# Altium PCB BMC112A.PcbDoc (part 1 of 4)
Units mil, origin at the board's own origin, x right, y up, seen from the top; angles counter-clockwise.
Board outline 5600 x 6100 mil, 8 copper layers (Top Layer, Signal Layer 1, Signal Layer 2, Signal Layer 3, Signal Layer 4, Signal Layer 5, Signal Layer 6, Bottom Layer), stack 62.048 mil thick; 366 components, 158 nets, 872 pads, 1045 vias.
Unrouted connection lines stored in the file: 4.
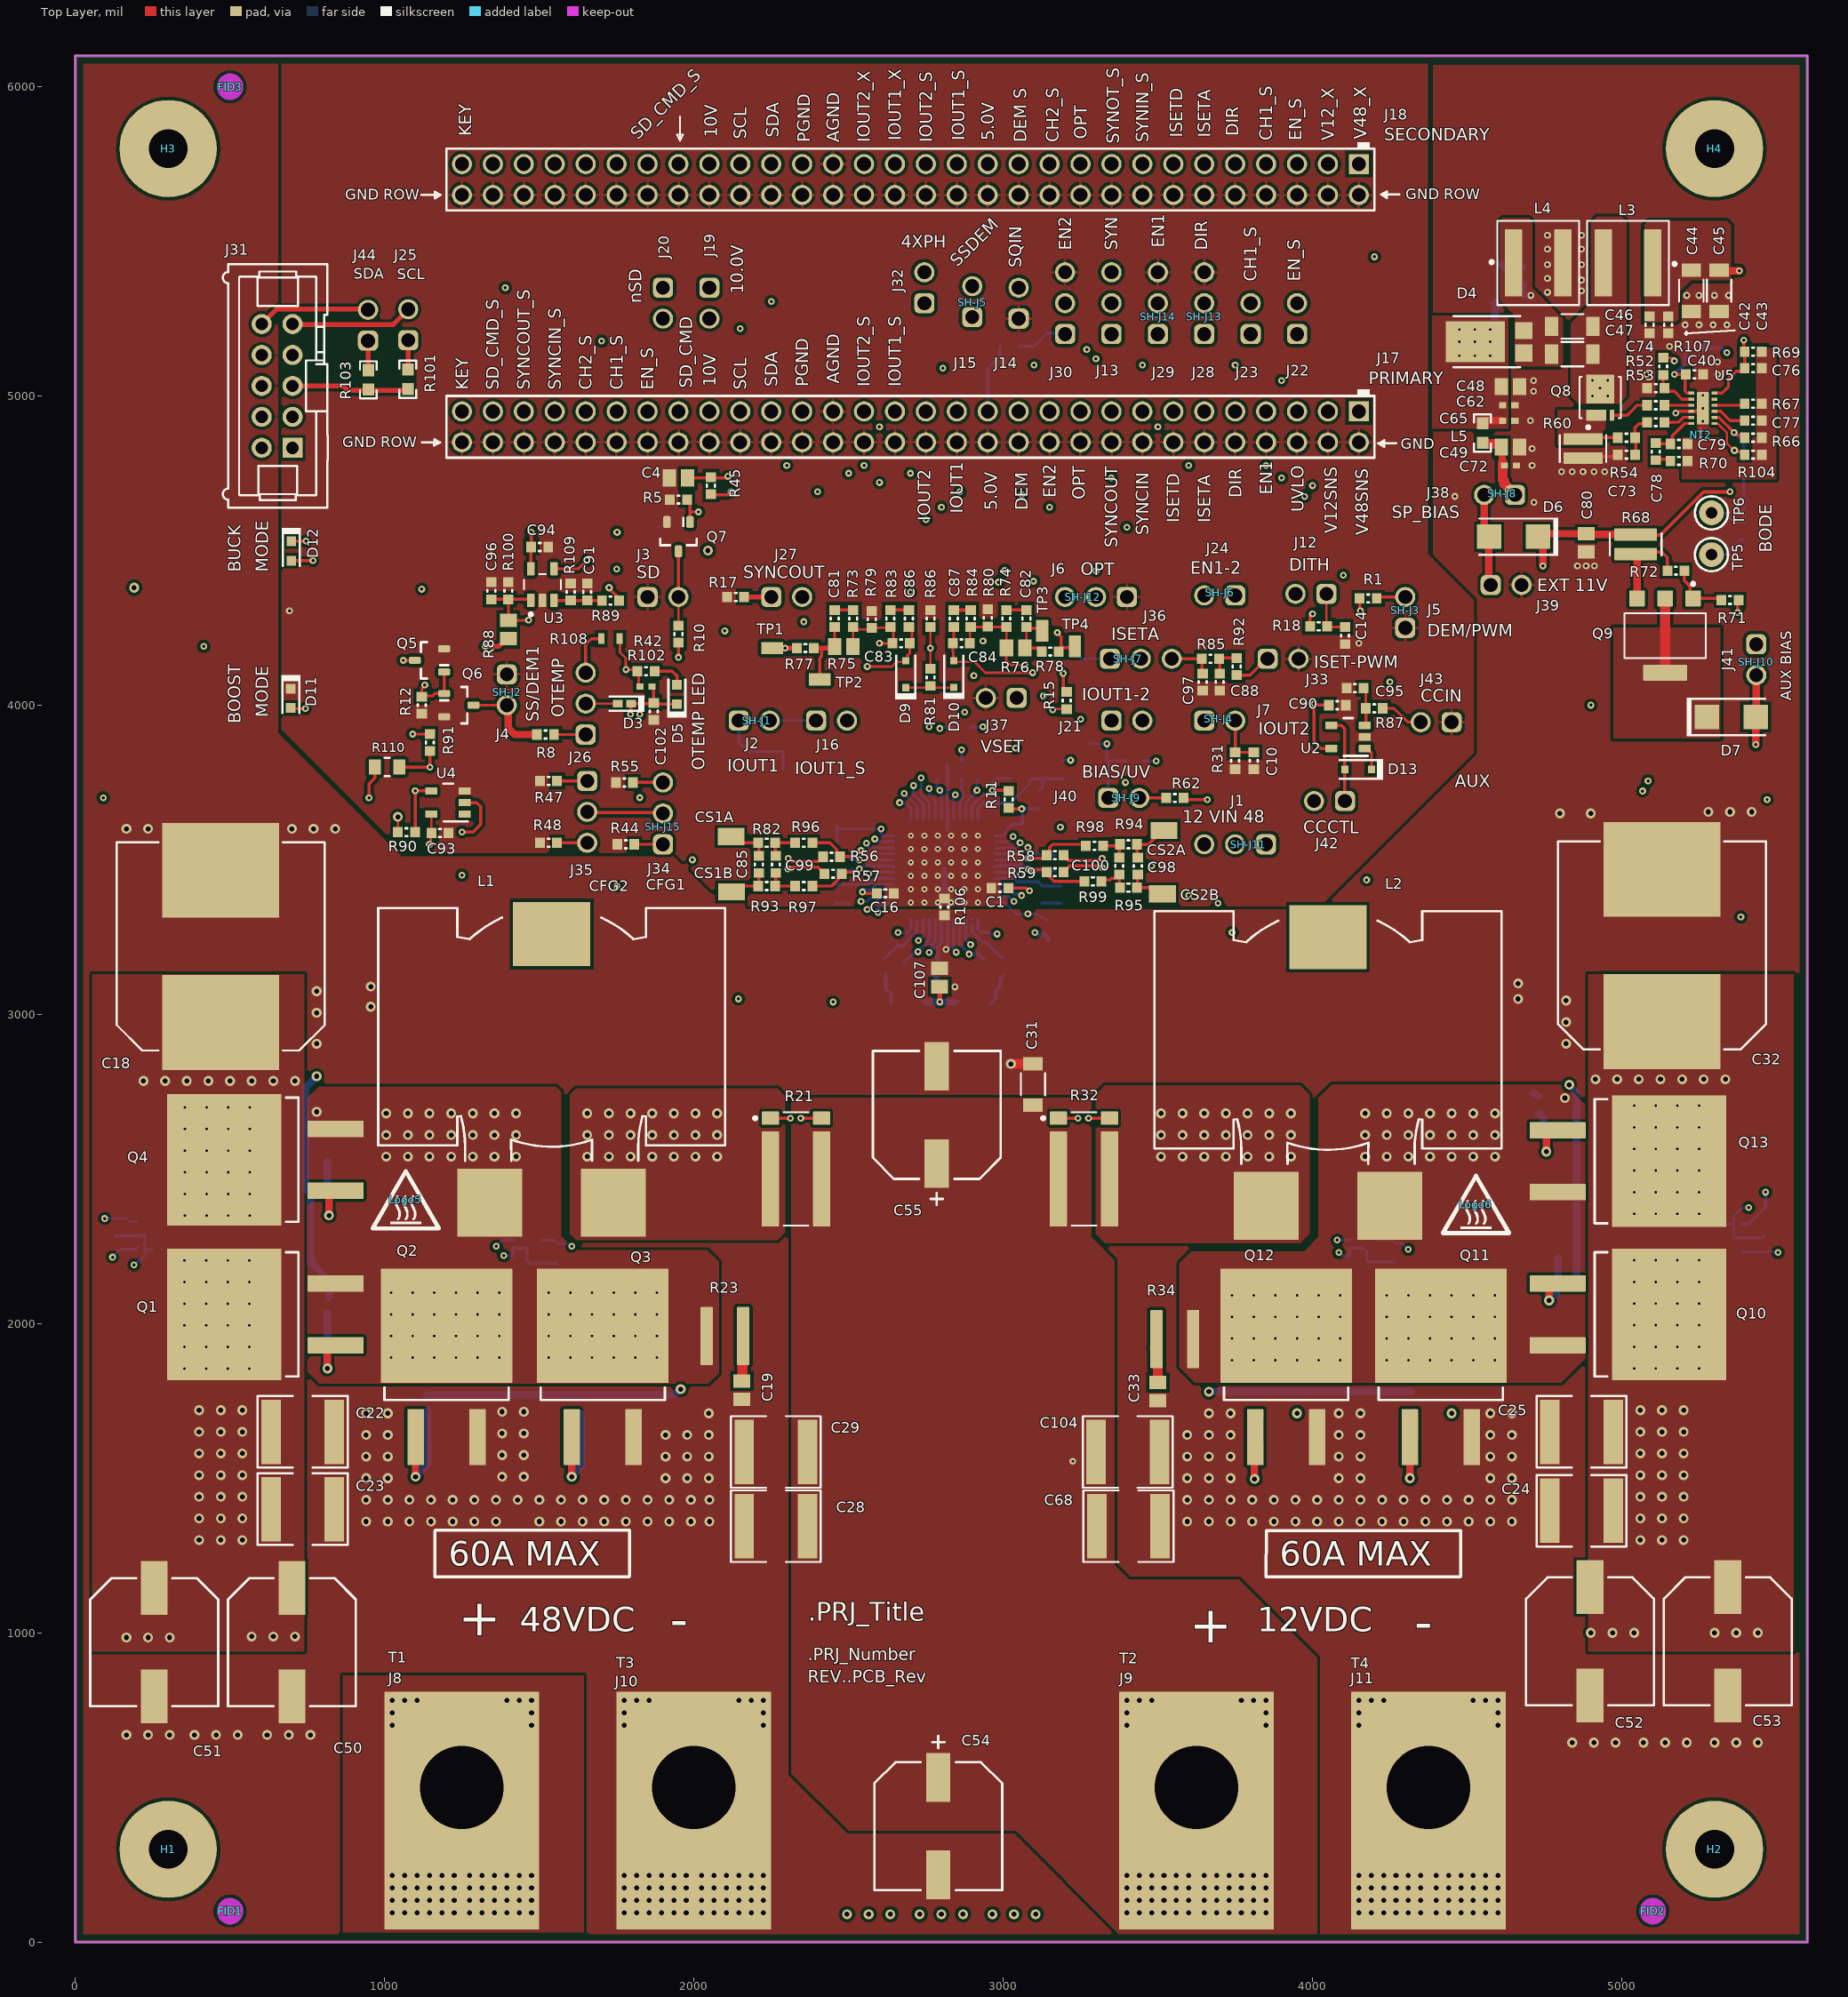
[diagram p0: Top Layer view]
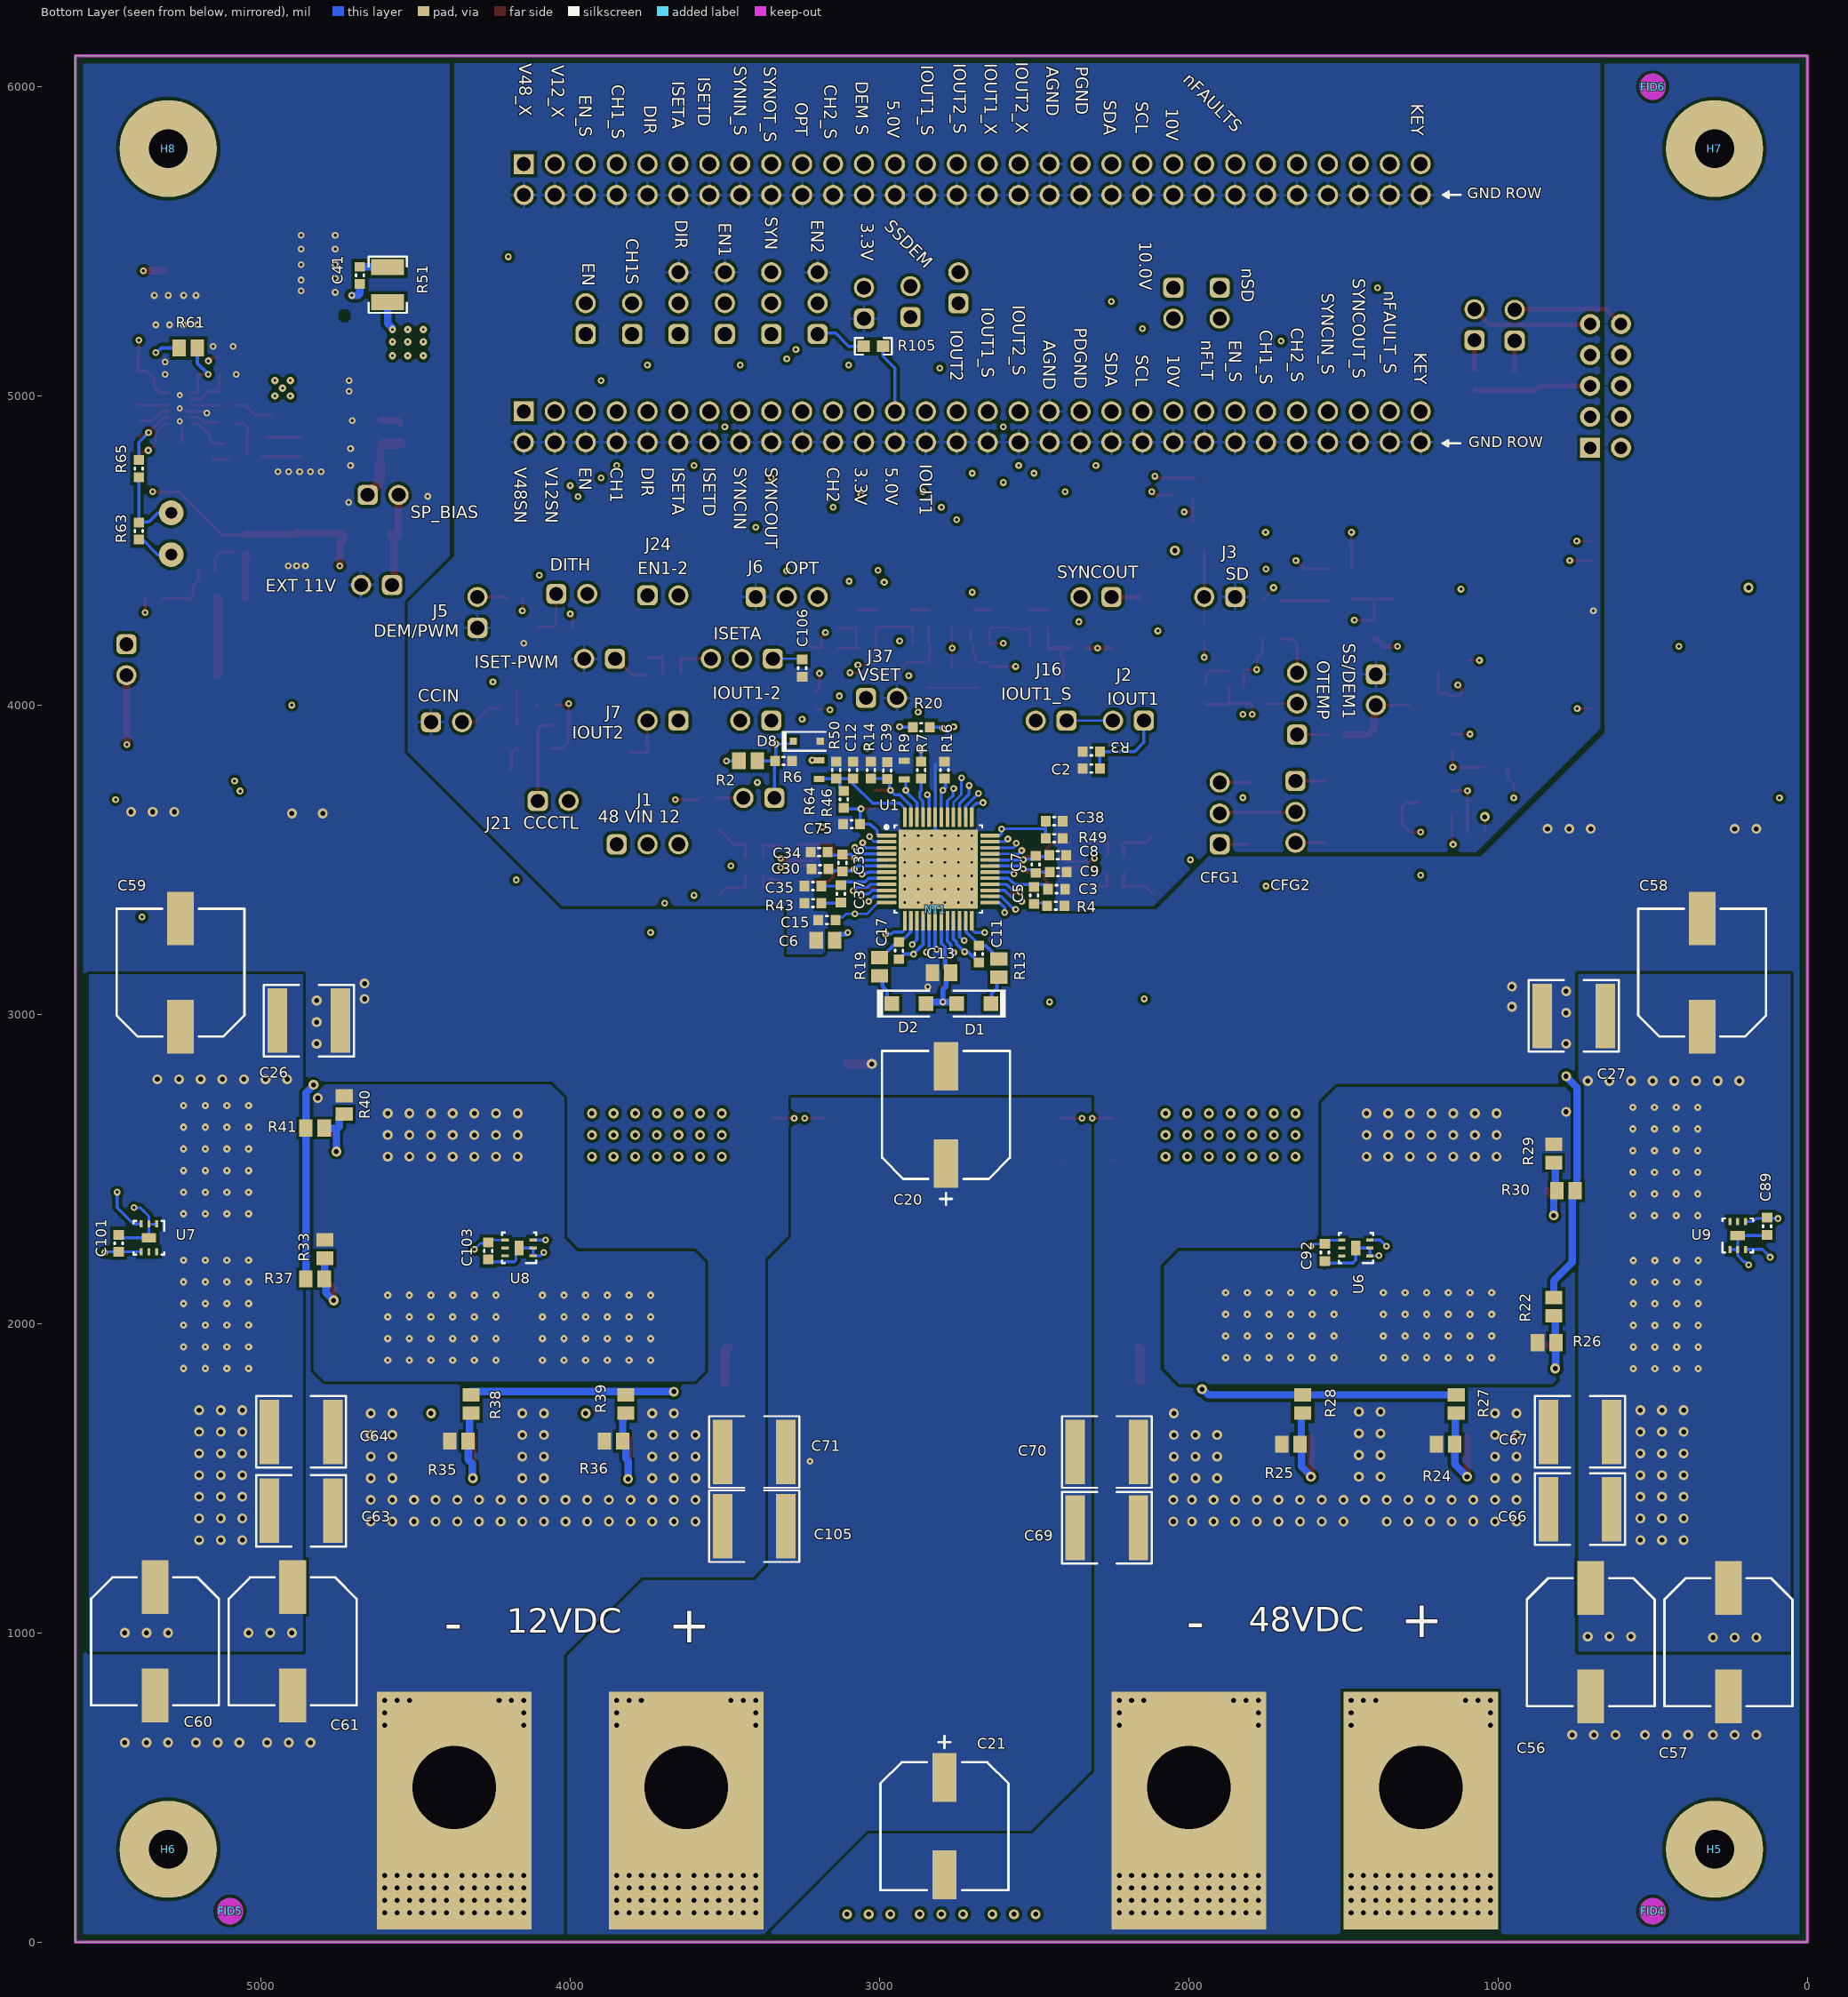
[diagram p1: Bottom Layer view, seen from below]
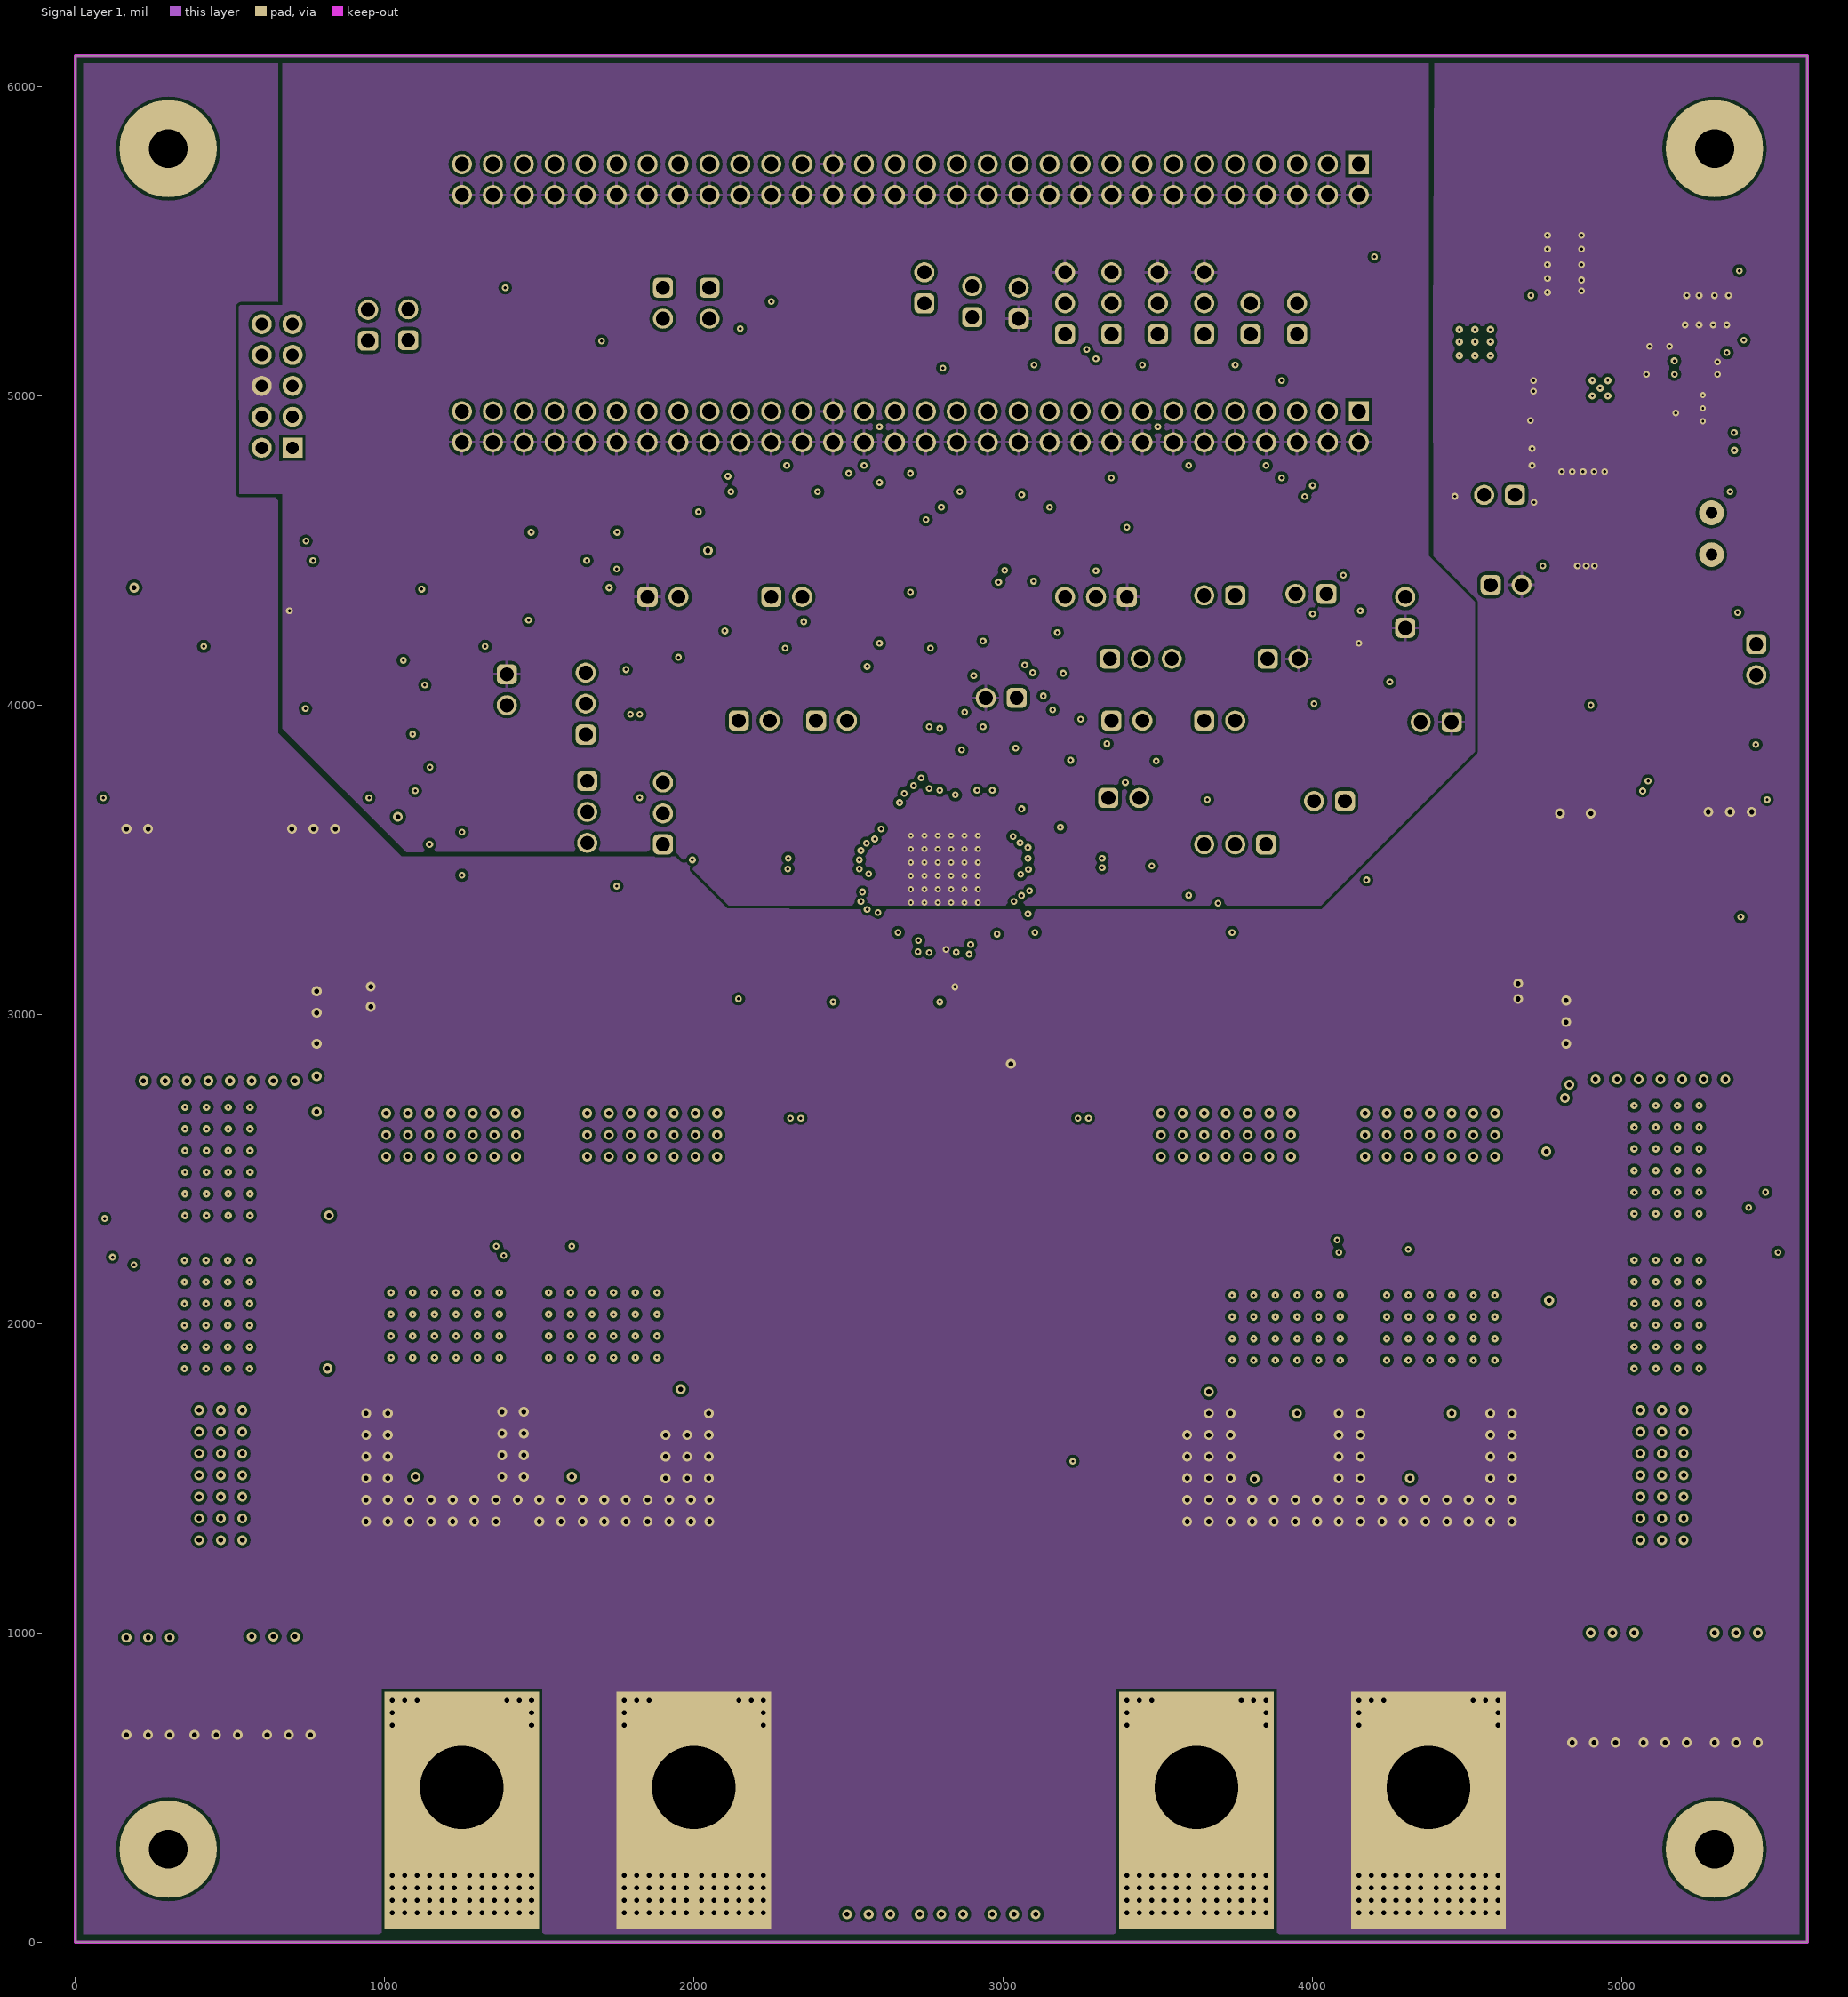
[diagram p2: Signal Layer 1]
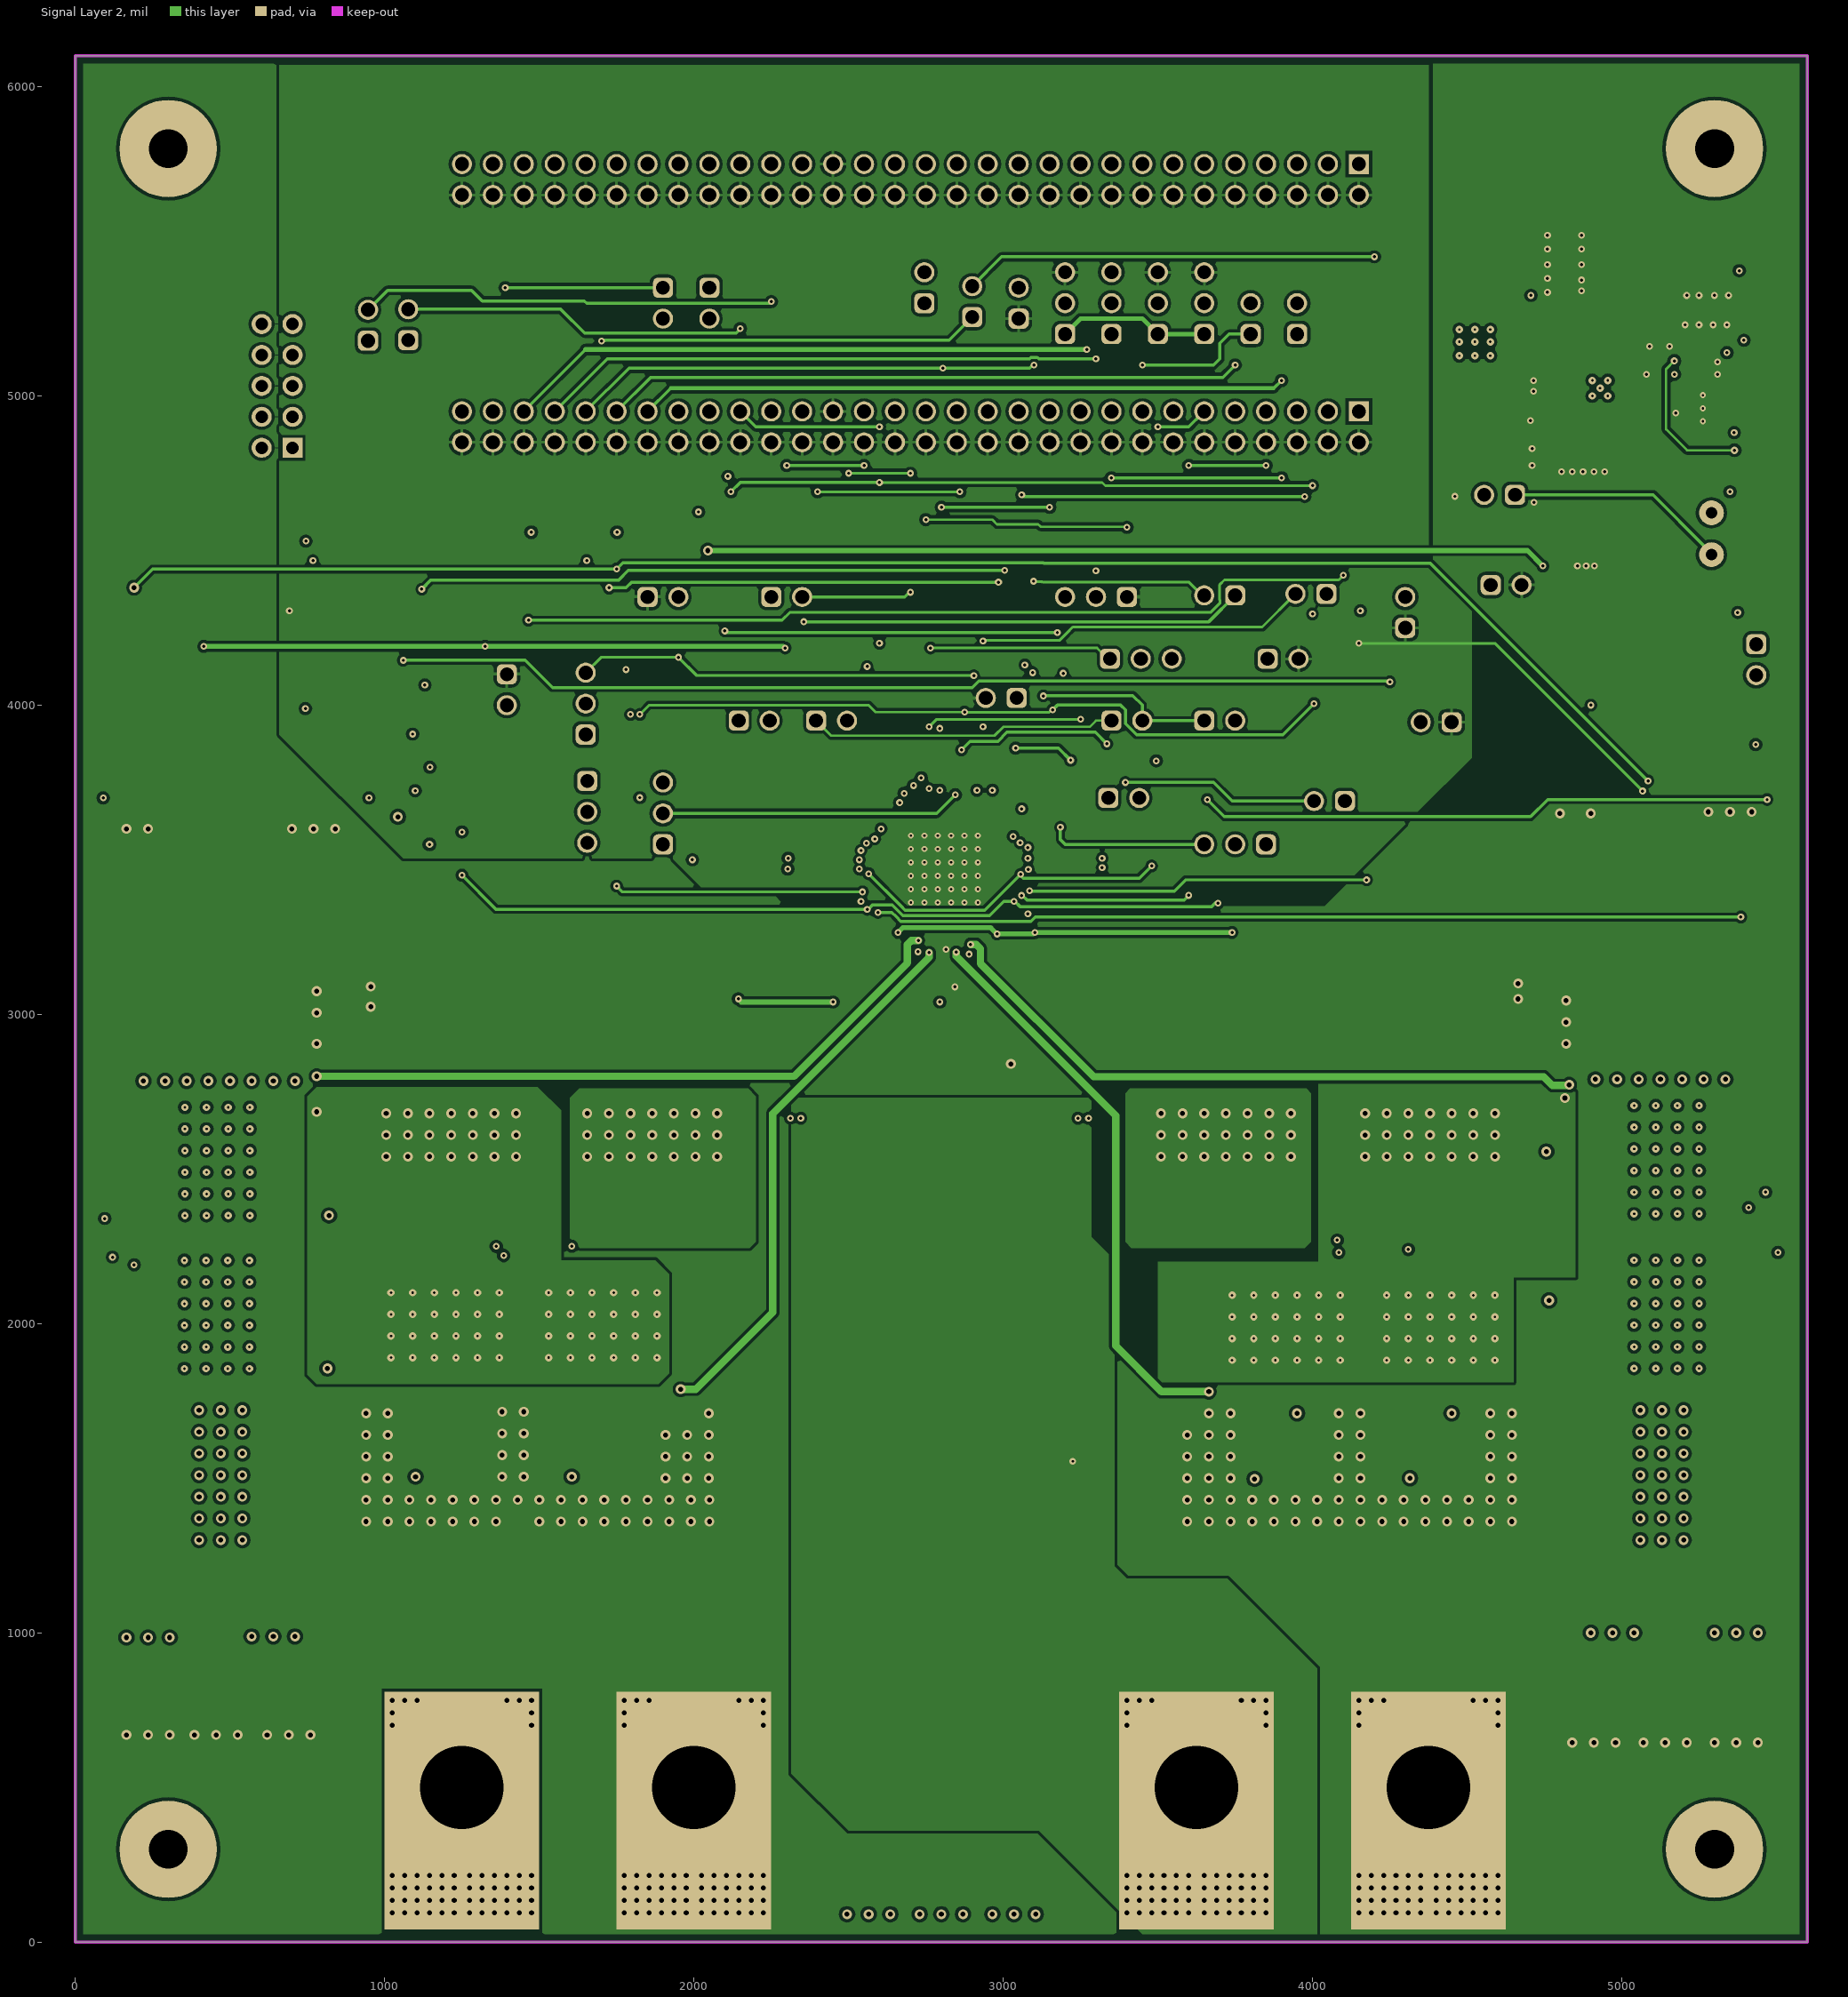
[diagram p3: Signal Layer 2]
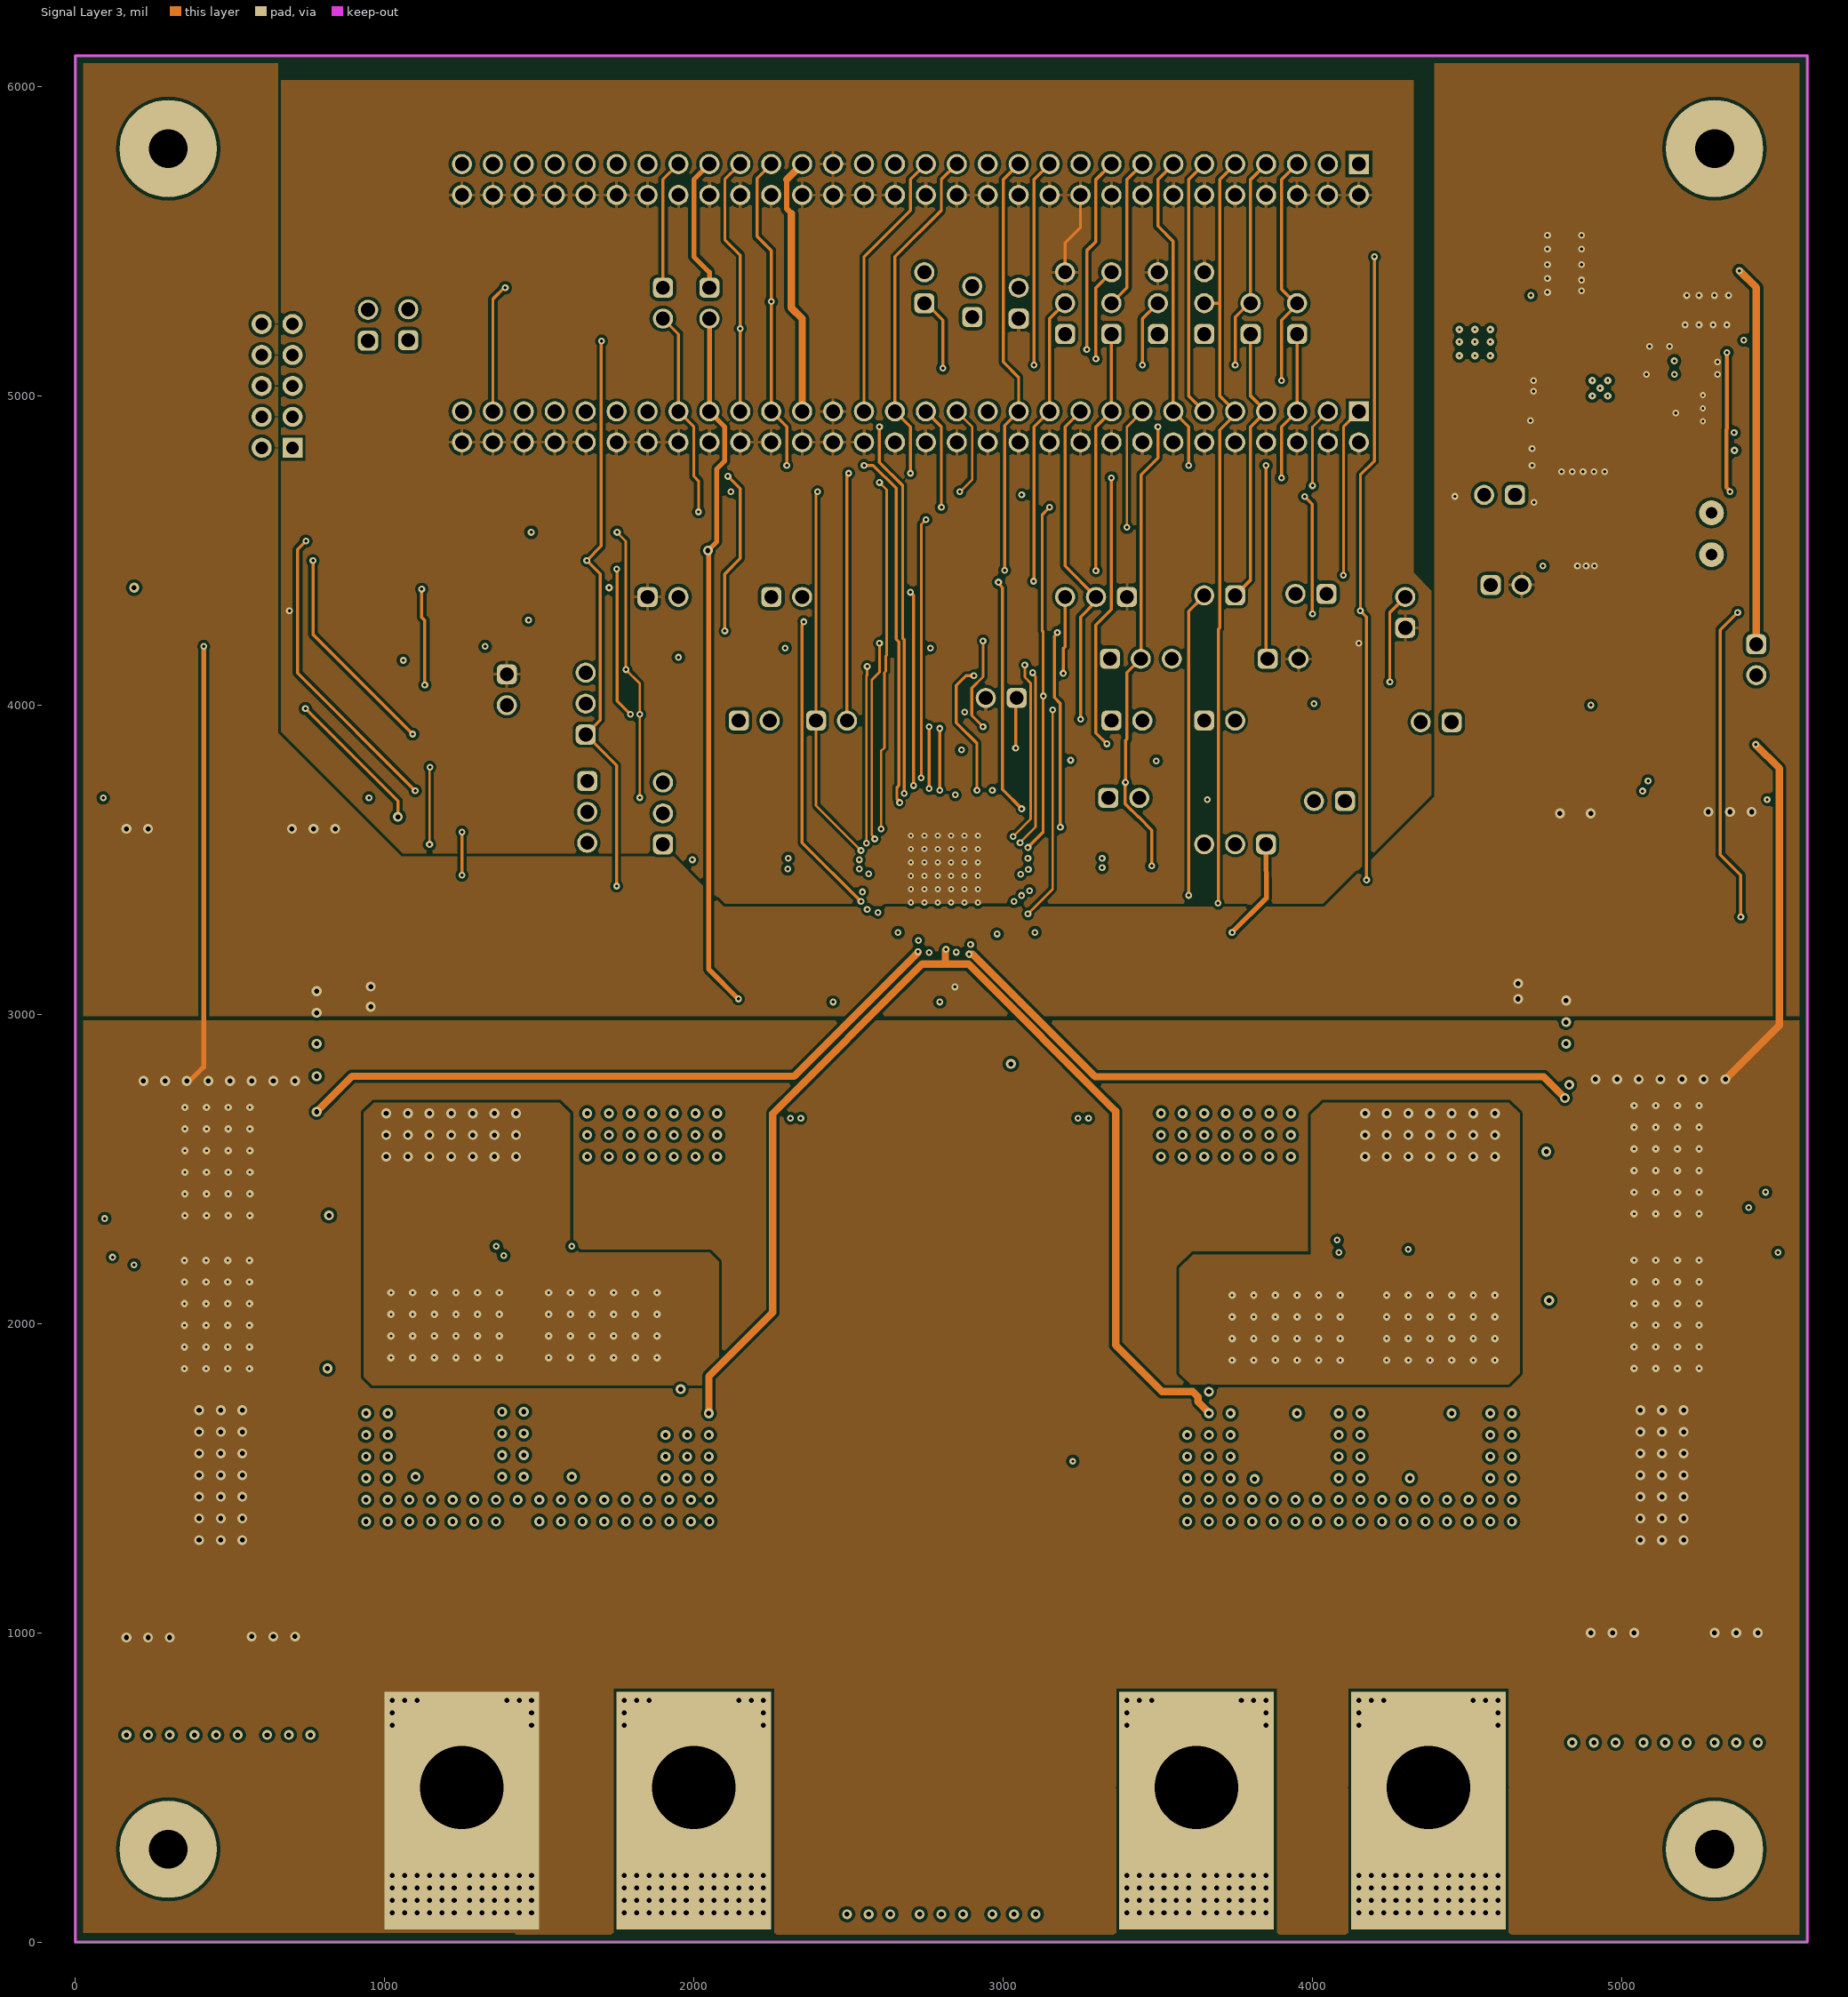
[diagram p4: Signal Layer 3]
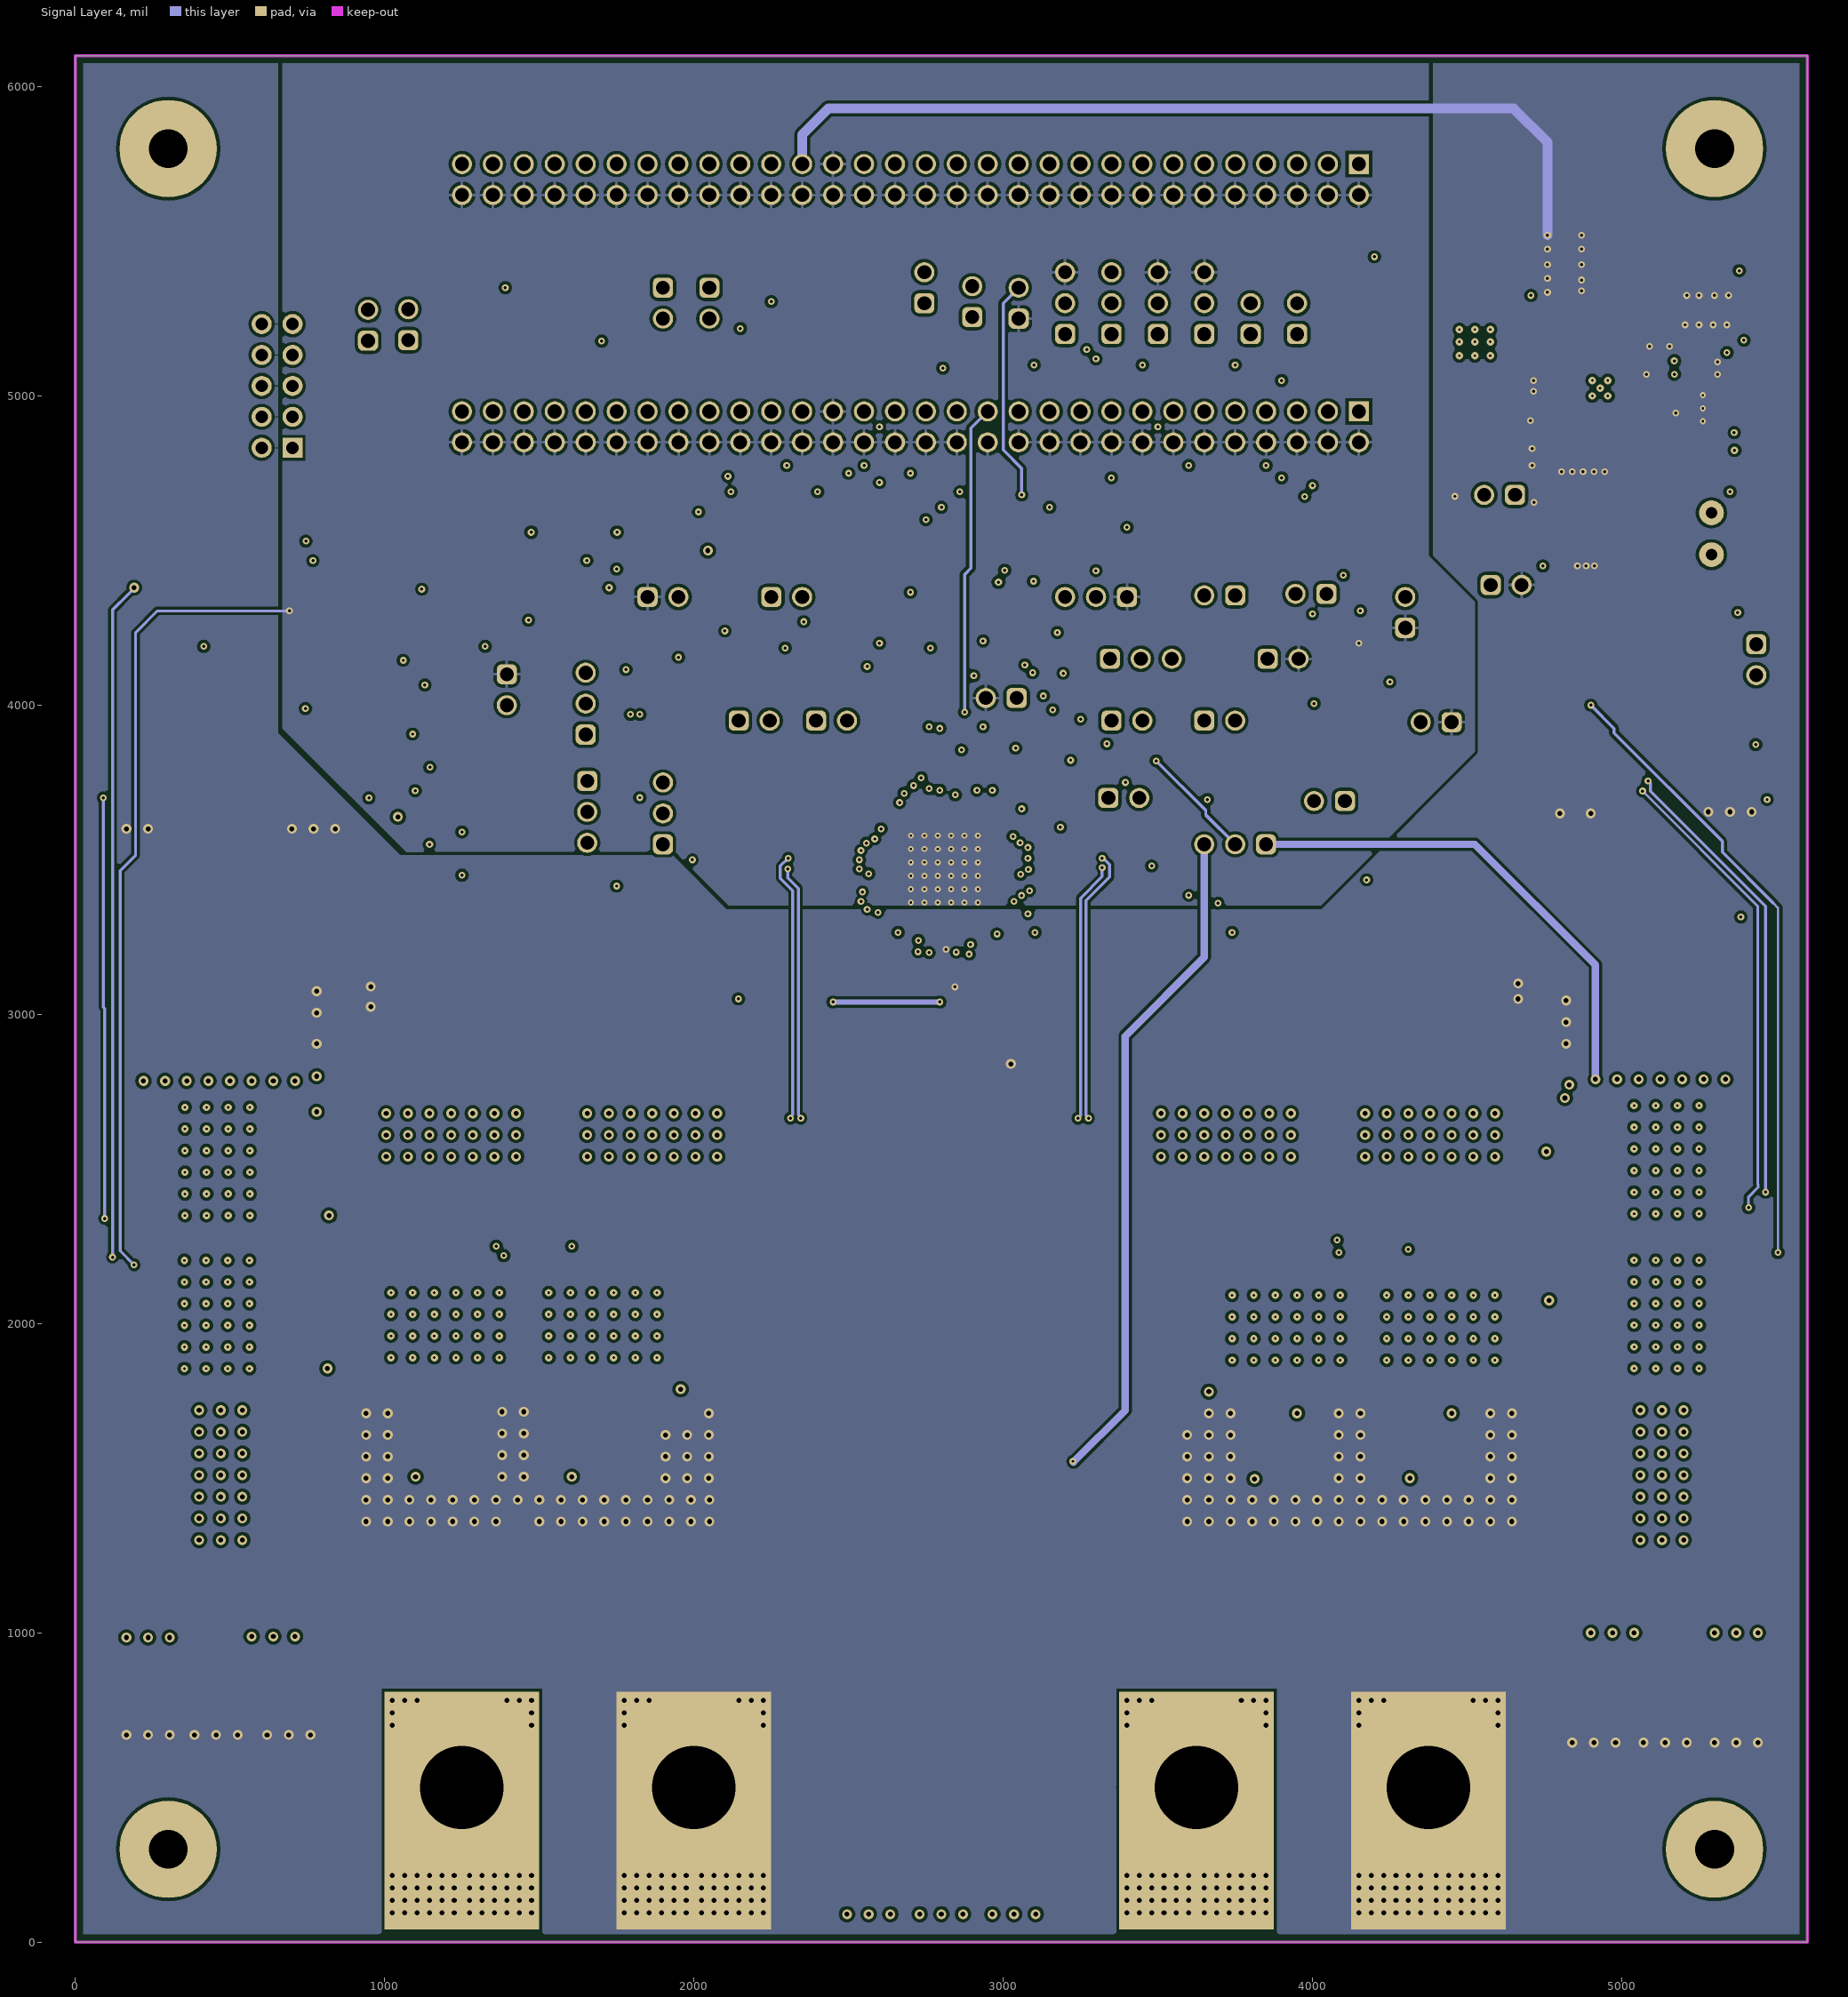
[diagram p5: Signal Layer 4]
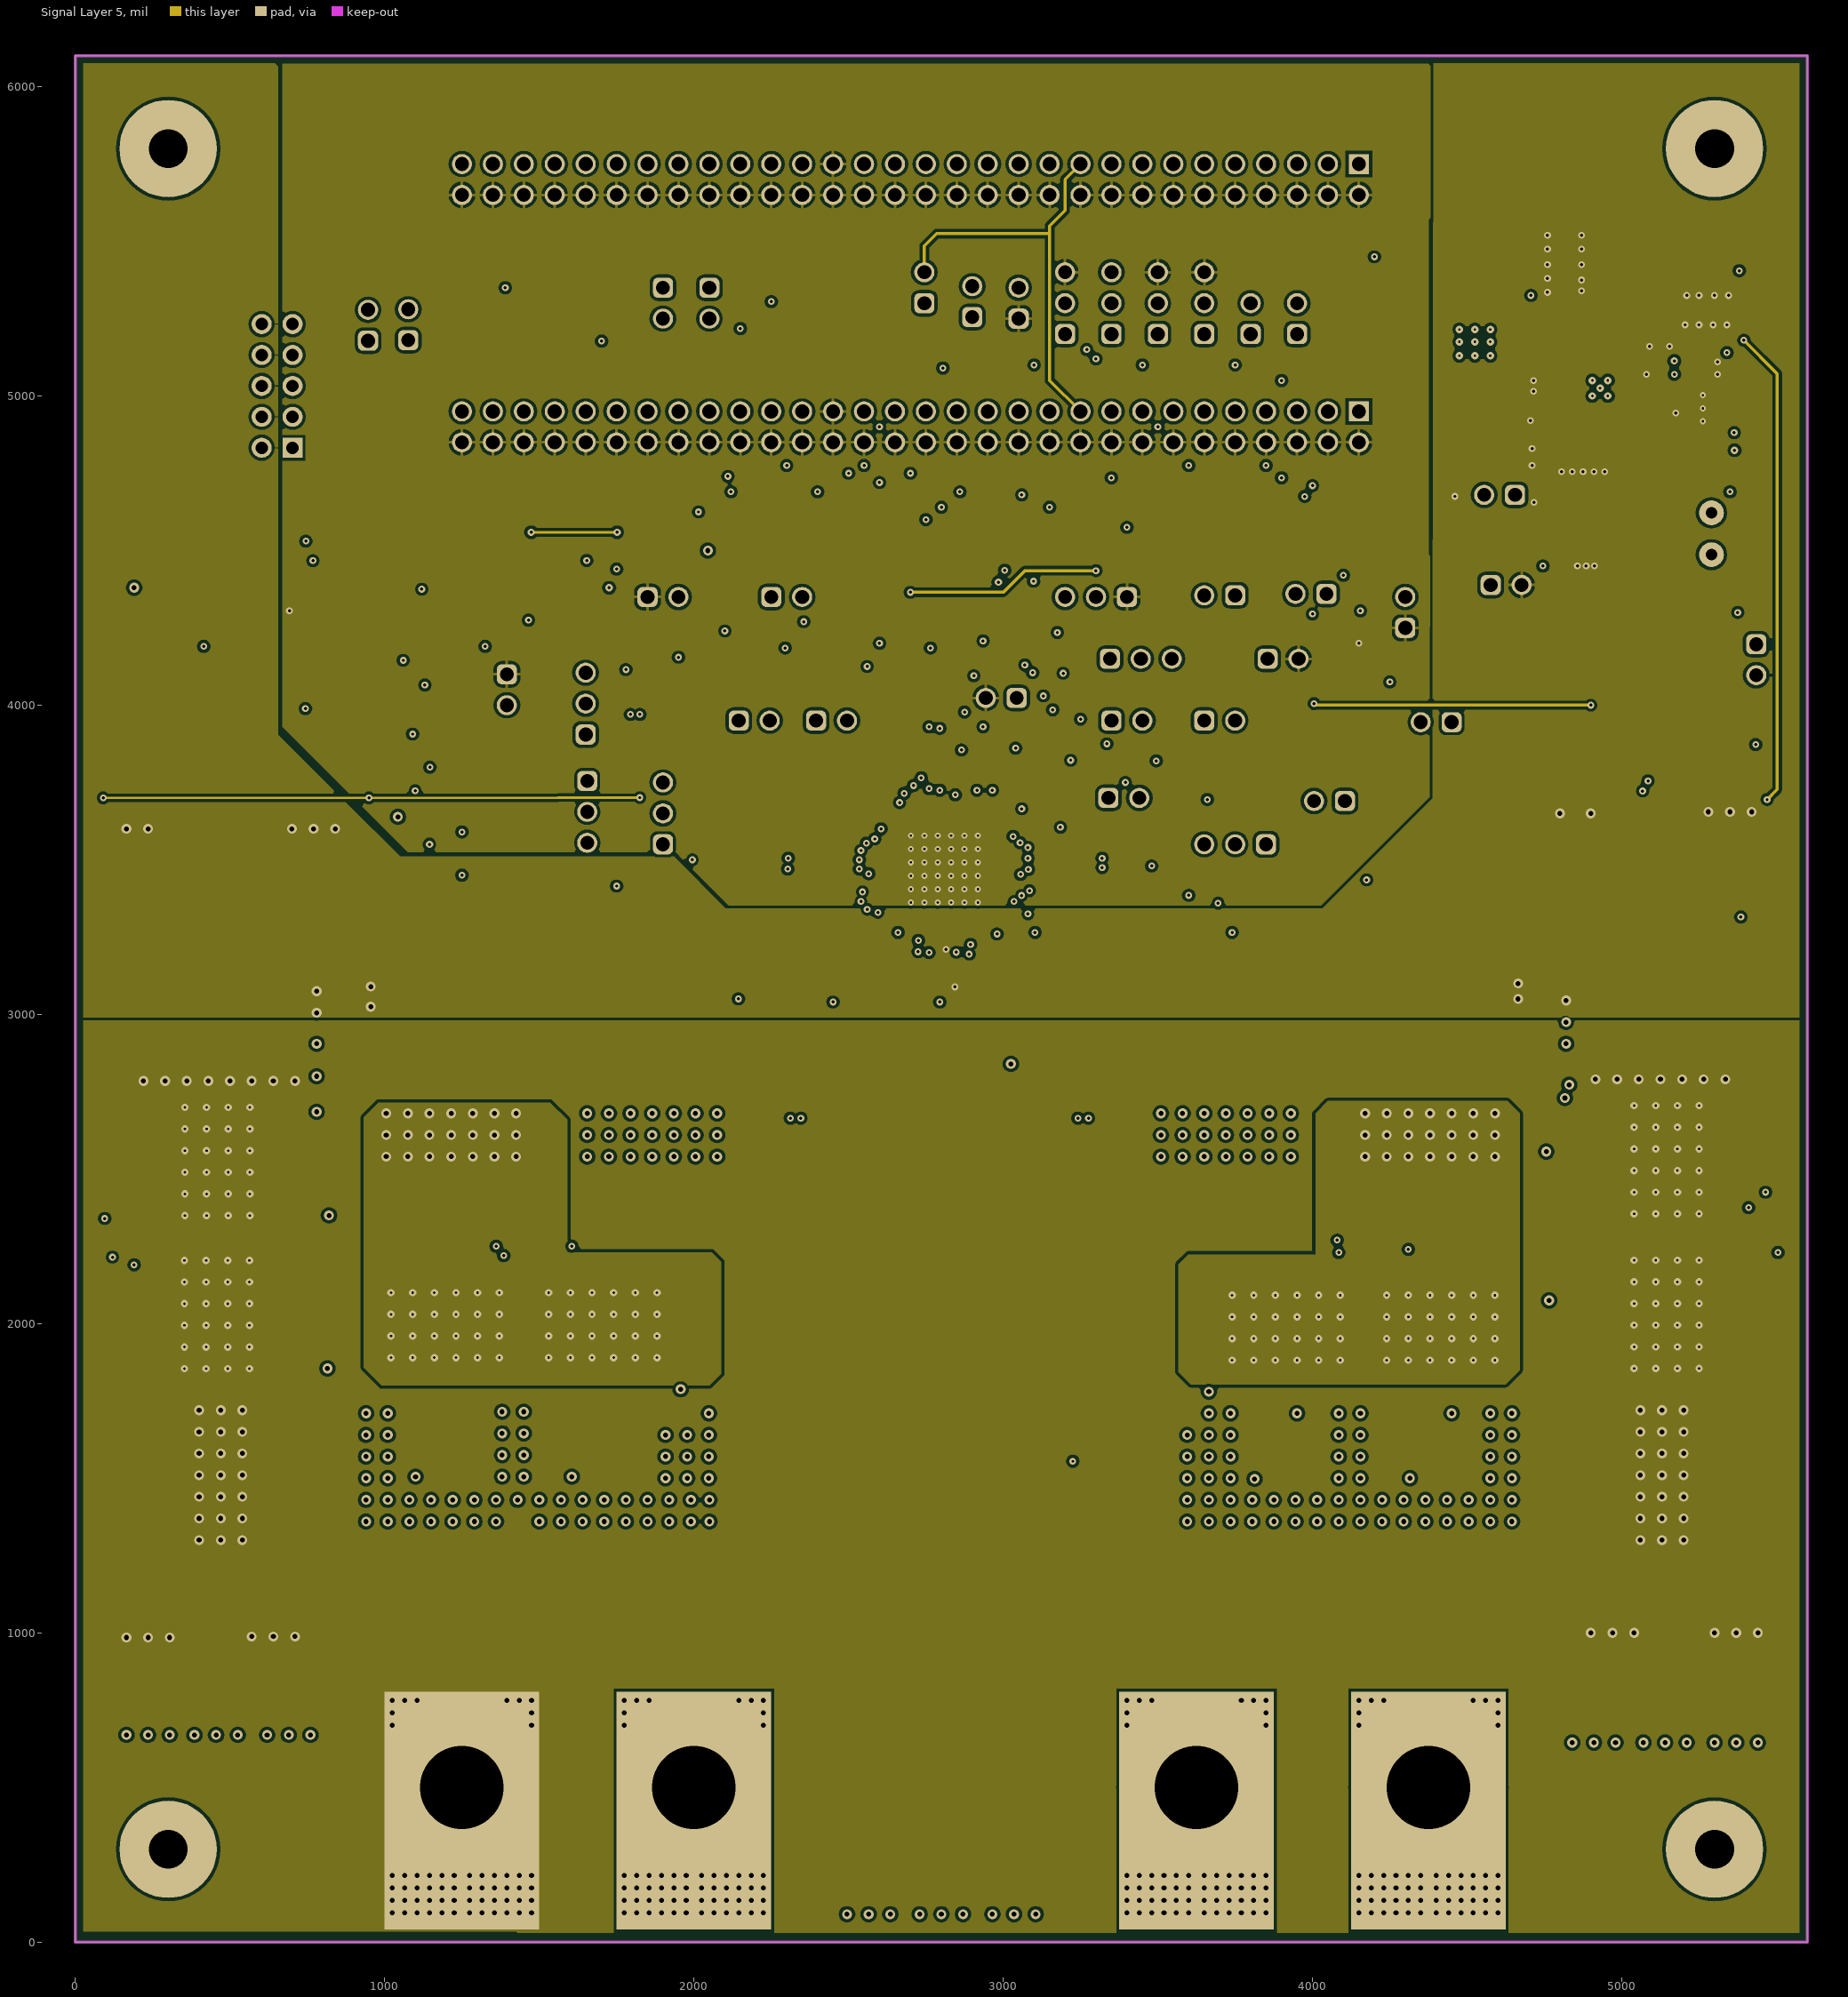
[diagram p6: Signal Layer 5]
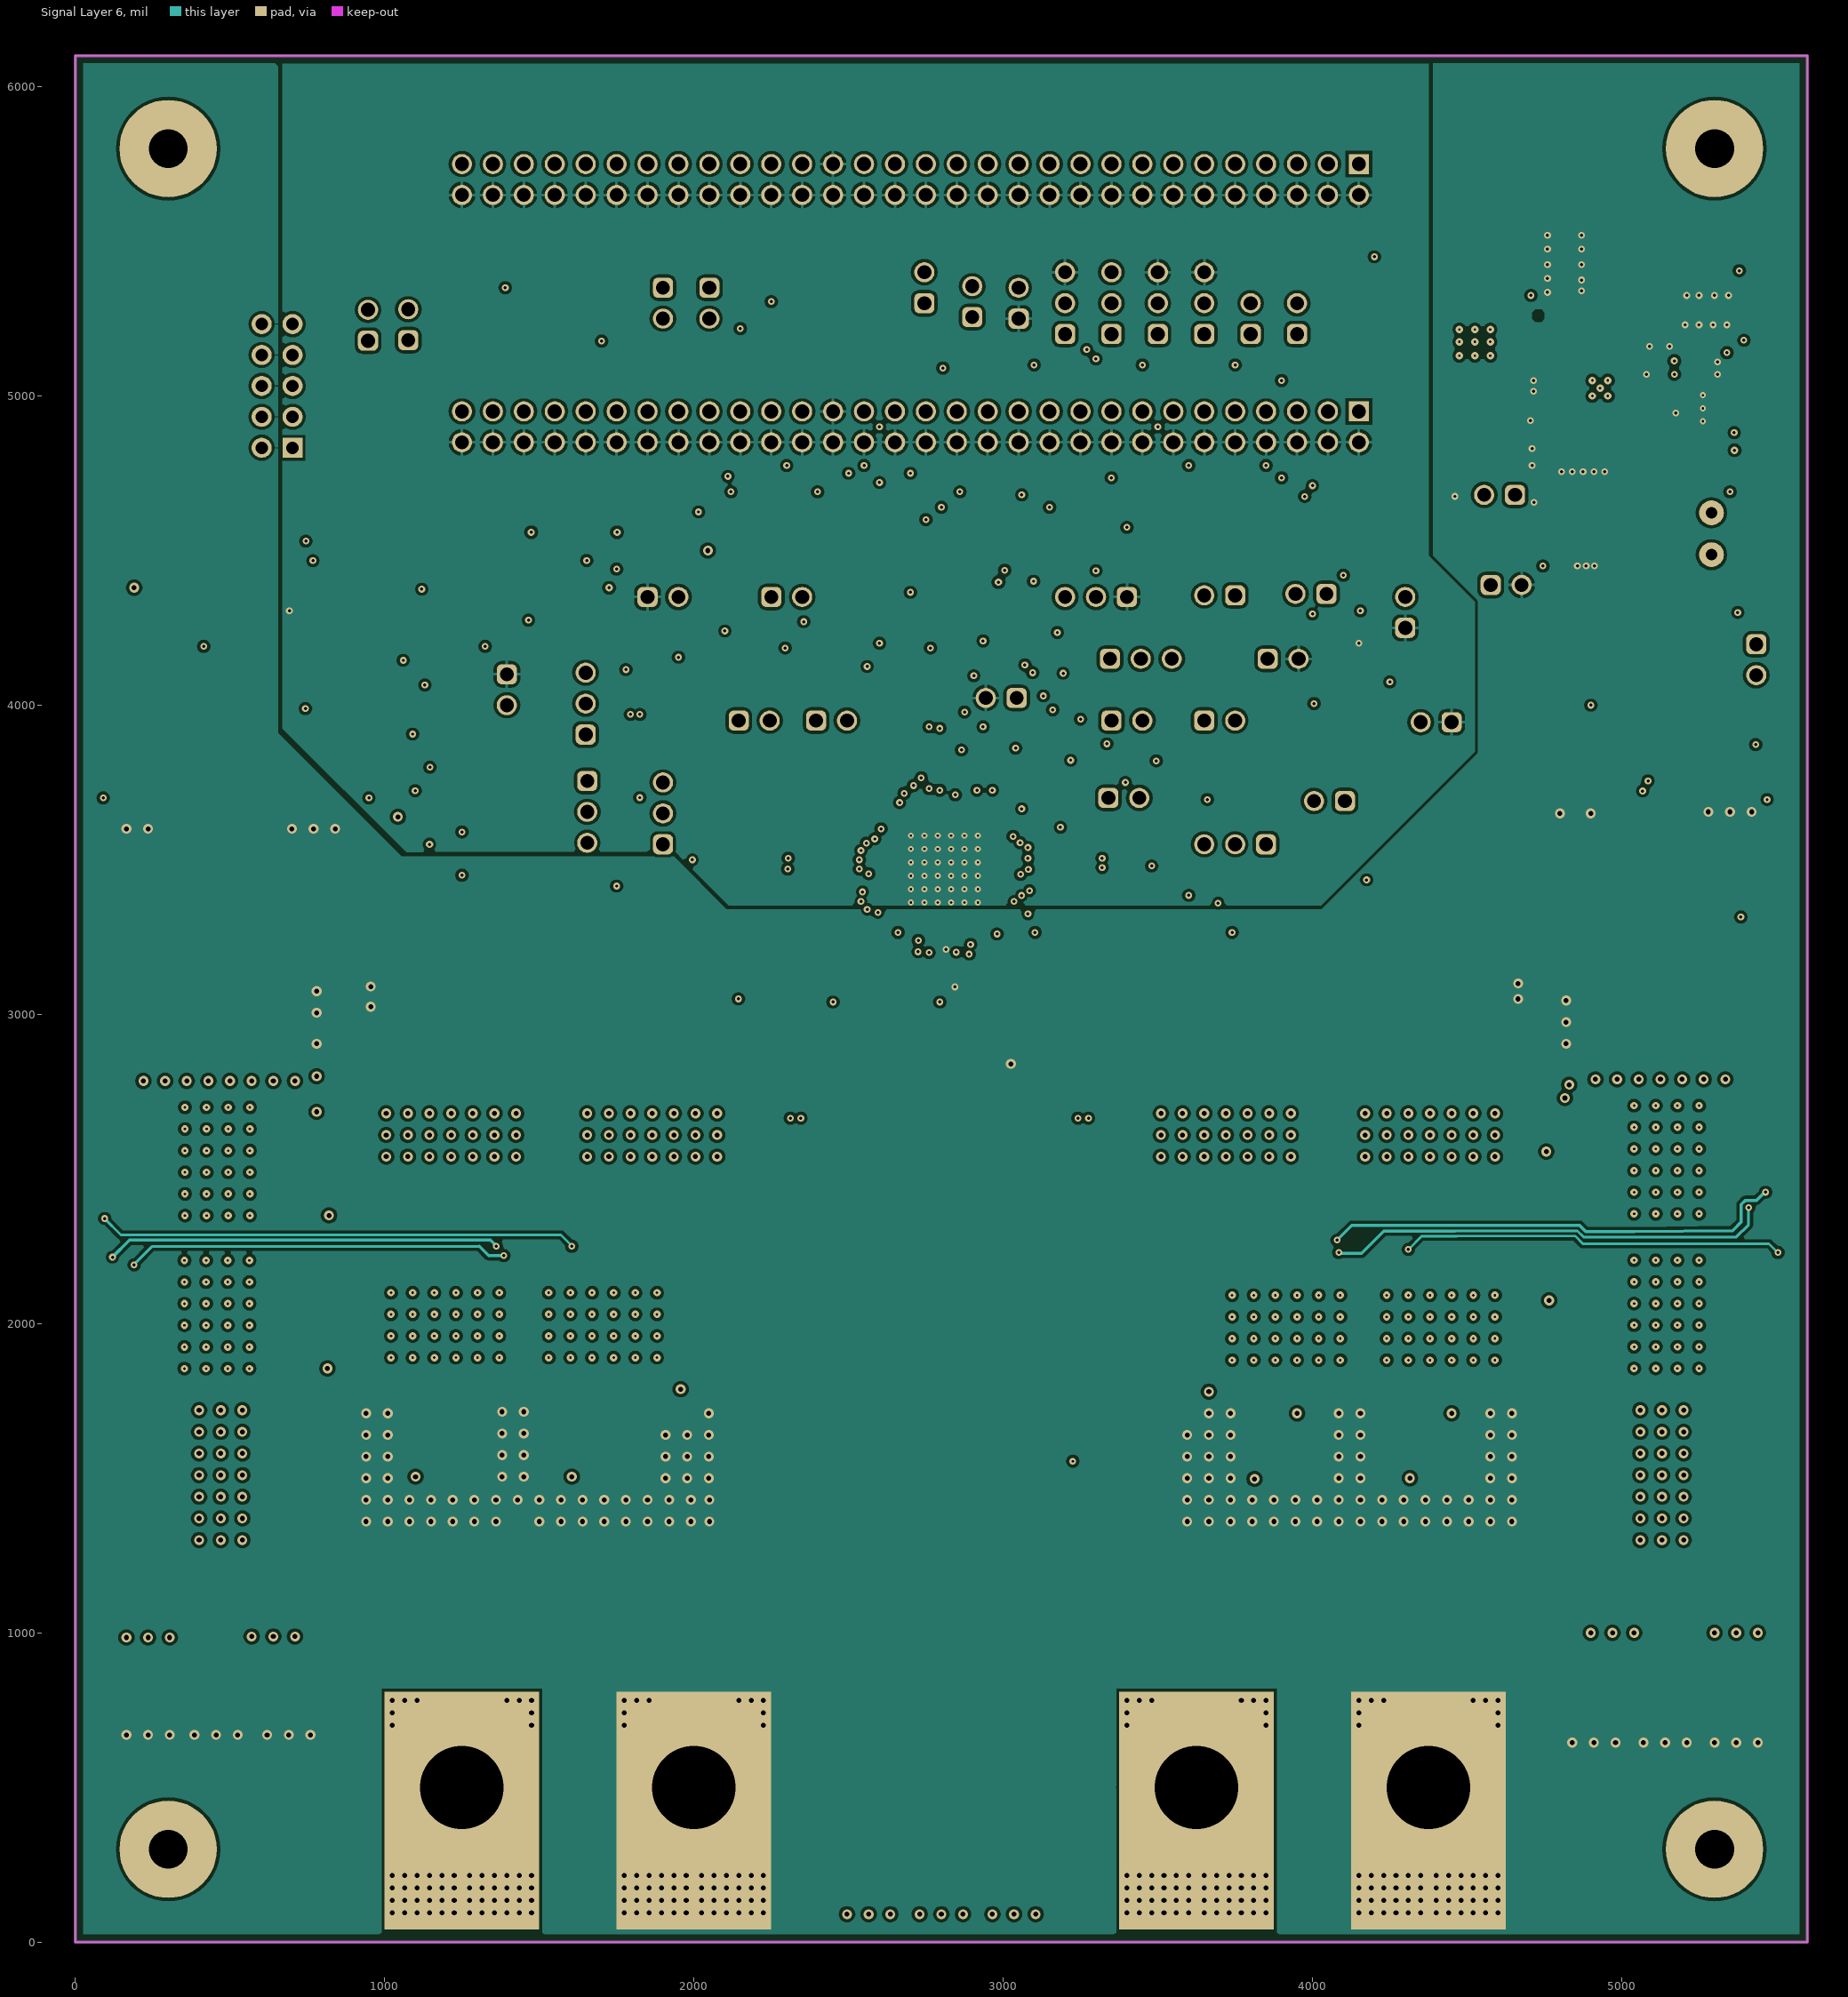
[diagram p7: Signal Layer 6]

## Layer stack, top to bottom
Top Solder: solder mask 0.4, Solder Resist, Dk 3.5
Top Layer: signal copper 2.756
Dielectric1: prepreg 5, FR-4 High Tg, Dk 4.8
Signal Layer 1: signal copper 2.756
Dielectric2: dielectric 5, FR-4 High Tg, Dk 4.8
Signal Layer 2: signal copper 2.756
Dielectric3: dielectric 5, FR-4 High Tg, Dk 4.8
Signal Layer 3: signal copper 2.756
Dielectric7: dielectric 10, FR-4 High Tg, Dk 4.8
Signal Layer 4: signal copper 2.756
Dielectric4: dielectric 5, FR-4 High Tg, Dk 4.8
Signal Layer 5: signal copper 2.756
Dielectric6: dielectric 5, FR-4 High Tg, Dk 4.8
Signal Layer 6: signal copper 2.756
Dielectric5: prepreg 5, FR-4 High Tg, Dk 4.8
Bottom Layer: signal copper 2.756
Bottom Solder: solder mask 0.4, Solder Resist, Dk 3.5

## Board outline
0,0 0,6100 5600,6100 5600,0

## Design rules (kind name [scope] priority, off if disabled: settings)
AcuteAngle [All] p1: minimum=4.50000000000000E+0001 checktracksonly=FALSE
AssemblyTestPointUsage [All] p1: valid=2
BoardOutlineClearance BoardOutlineClearance_Test [IsText] p1: gap=0 ignorepadtopadclearanceinfootprint=FALSE
BoardOutlineClearance BoardOutlineClearance_MountingHoles [OnCopper and InComponentClass('Mounting Holes')] p2: gap=39.37 ignorepadtopadclearanceinfootprint=FALSE
BoardOutlineClearance BoardOutlineClearance_Poly [OnCopper and IsPoly] p3: gap=25 ignorepadtopadclearanceinfootprint=FALSE
BoardOutlineClearance [OnCopper and Not InComponentClass('Logo') and not InComponentClass('FiducialMark') and not InRegion(1000,500,4000,800) and not InPoly] p4: gap=40 ignorepadtopadclearanceinfootprint=FALSE
Clearance Clearance_Keepouts [((IsTrack Or IsArc) And Not InPoly) And IsFree and IsKeepOut vs ((IsTrack Or IsArc) And Not InPoly) And IsFree and IsKeepOut] p1: gap=0 ignorepadtopadclearanceinfootprint=FALSE
Clearance Clearance_Poly [InPolygon] p2: gap=10 ignorepadtopadclearanceinfootprint=TRUE
Clearance Clearance_FiducialMark [IsKeepOut and InComponentClass('FiducialMark') vs IsPad and InComponentClass('FiducialMark')] p3: gap=0 ignorepadtopadclearanceinfootprint=FALSE
Clearance [All] p4: gap=7.87 ignorepadtopadclearanceinfootprint=TRUE
ComponentClearance ComponentClearance_MountingHoles_FiducialMarks [InComponentClass('Mounting Holes') vs InComponentClass('FiducialMark')] p1: gap=50 collisioncheckmode=3 verticalgap=10 showdistances=FALSE
ComponentClearance ComponentClearance_Shunt [HasFootprint('Harwin_M7582-05') vs InComponentClass('Header')] p2: gap=0 collisioncheckmode=3 verticalgap=0 showdistances=FALSE
ComponentClearance ComponentClearance_Logo [InComponentClass('Logo')] p3: gap=30 collisioncheckmode=3 verticalgap=10 showdistances=FALSE
ComponentClearance ComponentClearance_ScrewToNut [(HasFootprint('NY PMS 440 0025 PH')) vs (HasFootprint('Keystone_1902C'))] p4: gap=5 collisioncheckmode=3 verticalgap=10 showdistances=FALSE
ComponentClearance ComponentClearance_MountingHoles [InComponentClass('Mounting Holes')] p5: gap=100 collisioncheckmode=3 verticalgap=100000 showdistances=FALSE
ComponentClearance ComponentClearance_SmallPassives [HasFootprint('0201*') or HasFootprint('0402*') or HasFootprint('0508') or HasFootprint('0603*') or HasFootprint('0612') or HasFootprint('0805*') or HasFootprint('0815*') or HasFootprint('0830*') or HasFootprint('1206*') or HasFootprint('1210*') or HasFootprint('1808*') or HasFootprint('1812*') or HasFootprint('1825*') or HasFootprint('2010*') or HasFootprint('2220*') or HasFootprint('2225*') or HasFootprint('2512*') or HasFootprint('2728*') or HasFootprint('3518*') vs HasFootprint('0201*') or HasFootprint('0402*') or HasFootprint('0508') or HasFootprint('0603*') or HasFootprint('0612') or HasFootprint('0805*') or HasFootprint('0815*') or HasFootprint('0830*') or HasFootprint('1206*') or HasFootprint('1210*') or HasFootprint('1808*') or HasFootprint('1812*') or HasFootprint('1825*') or HasFootprint('2010*') or HasFootprint('2220*') or HasFootprint('2225*') or HasFootprint('2512*') or HasFootprint('2728*') or HasFootprint('3518*')] p6: gap=14.96 collisioncheckmode=3 verticalgap=10 showdistances=FALSE
ComponentClearance ComponentClearance_THtoSMT [IsThruComponent vs IsSMTComponent] p7: gap=20 collisioncheckmode=3 verticalgap=30 showdistances=FALSE
ComponentClearance ComponentClearance_Lug2Banana [InComponent('T1') or InComponent('T2') or InComponent('T3') or InComponent('T4')] p8: gap=0 collisioncheckmode=3 verticalgap=0 showdistances=FALSE
ComponentClearance ComponentClearance_THtoTH [IsThruComponent vs IsThruComponent] p9: gap=20 collisioncheckmode=3 verticalgap=30 showdistances=FALSE
ComponentClearance ComponentClearance_NetTie [HasFootprint('Net-Tie_10mil')] p10: gap=0 collisioncheckmode=3 verticalgap=0 showdistances=FALSE
ComponentClearance [All] p11: gap=15 collisioncheckmode=3 verticalgap=10 showdistances=FALSE
DiffPairsRouting [All] p1: maxlimit=100 minlimit=10 mostfreqgap=10 toplayer_minwidth=15 toplayer_maxwidth=15 toplayer_prefwidth=15 midlayer1_minwidth=15 midlayer1_maxwidth=15 midlayer1_prefwidth=15 midlayer2_minwidth=15 midlayer2_maxwidth=15 midlayer2_prefwidth=15 midlayer3_minwidth=15 midlayer3_maxwidth=15 midlayer3_prefwidth=15 midlayer4_minwidth=15 midlayer4_maxwidth=15 midlayer4_prefwidth=15 midlayer5_minwidth=15 midlayer5_maxwidth=15 midlayer5_prefwidth=15 midlayer6_minwidth=15 midlayer6_maxwidth=15 midlayer6_prefwidth=15 bottomlayer_minwidth=15 bottomlayer_maxwidth=15 bottomlayer_prefwidth=15 maxuncoupledlength=1000
FabricationTestPointUsage TestPointUsage [All] p1: valid=2 allowmultiple=FALSE
FabricationTestpoint Testpoint [All] p1: side=3 testpointundercomponent=TRUE minsize=40 maxsize=100 preferedsize=60 minholesize=0 maxholesize=40 preferedholesize=32 testpointgrid=1 allowsidetop=TRUE allowsidebottom=TRUE usegrid=TRUE gridtolerance=0.01
FanoutControl Fanout_LCC [IsLCC] p1: bgadir=Out bgaviamode=Centered fanoutstyle=Auto fanoutdirection=Alternating viagrid=1 // Fanout_LCC (Default Rule)
FanoutControl Fanout_BGA [IsBGA] p2: bgadir=Out bgaviamode=Centered fanoutstyle=Auto fanoutdirection=Alternating viagrid=1 // Fanout_BGA (Default Rule)
FanoutControl Fanout_Default [All] p4: bgadir=Out bgaviamode=Centered fanoutstyle=Auto fanoutdirection=Alternating viagrid=1 // Fanout_Default (Default Rule)
FanoutControl Fanout_Small [(CompPinCount < 5)] p5: bgadir=Out bgaviamode=Centered fanoutstyle=Auto fanoutdirection=OutThenIn viagrid=1 // Fanout_Small (Default Rule)
HoleSize [All] p1: absolutevalues=TRUE maxlimit=270 minlimit=7.87 maxpercent=80.000 minpercent=20.000
HoleToHoleClearance HoleToHoleClearance_Lugs [(HasFootprint('Panduit_CXS70-14-C') OR HasFootprint('FP-108-0740-102_CONN_BANANA_JACK-MFG'))] p1: gap=0 allowstackedmicrovias=TRUE
HoleToHoleClearance [All] p2: gap=10 allowstackedmicrovias=TRUE
MinimumAnnularRing MinimumAnnularRing_ThermalPadVias [IsVia and InAnyComponent] p1: minimumring=5.91
MinimumAnnularRing [All] p2: minimumring=6
MinimumSolderMaskSliver MinimumSolderMaskSliver_Logo [InComponentClass('Logo') vs InComponentClass('Logo')] p1: minsoldermaskwidth=0.7
MinimumSolderMaskSliver [All] p2: minsoldermaskwidth=3.94
PlaneConnect [All] p1: planeconnectstyle=Relief reliefexpansion=10 reliefentries=4 reliefconductorwidth=10 reliefairgap=10
PolygonConnect "PolygonConnect_TH Components" [(HasFootprint('SAMTEC_HMTSW-130-07-G-D-240') OR HasFootprint('WURTH_61300211121') OR HasFootprint('WURTH_61300311121'))] p1: connectstyle=Relief reliefconductorwidth=10 reliefentries=4 polygonreliefangle="90 Angle" airgapwidth=10
PolygonConnect [All] p2: connectstyle=Direct reliefconductorwidth=10 reliefentries=4 polygonreliefangle="90 Angle" airgapwidth=10
RoutingVias ThermalPadVias [IsVia and InAnyComponent] p1: holewidth=7.87 width=19.68 viastyle="Through Hole" minholewidth=7.87 minwidth=19.68 maxholewidth=18 maxwidth=34
RoutingVias [All] p2: holewidth=16 width=34 viastyle="Through Hole" minholewidth=7.87 minwidth=20 maxholewidth=40 maxwidth=65
SilkToBoardRegionClearance [Not ((IsComment or IsDesignator) And (Hide <> 'False')) and not InRegion(1000,500,4000,800)] p1:
SilkToSilkClearance SilkToSilkClearance_Pb-FreeLogo [(HasFootprint('Pb-Free_Overlay_Medium') OR HasFootprint('Pb-Free_Overlay_Small')) vs (HasFootprint('Pb-Free_Overlay_Medium') OR HasFootprint('Pb-Free_Overlay_Small'))] p1: silktosilkclearance=0
SilkToSilkClearance [All] p2: silktosilkclearance=3.94
SilkToSolderMaskClearance SilkToComponentPadClearance [(IsPad or IsFill or IsRegion) and InAnycomponent] p1: minsilkscreentomaskgap=5 clearancetoexposedcopper=TRUE
SilkToSolderMaskClearance "Silk to Solder Mask Opening" [All] p2: minsilkscreentomaskgap=3.94 clearancetoexposedcopper=FALSE
SolderMaskExpansion [All] p1: expansion=1.97 istentingtop=FALSE
UnRoutedNet [All] p1: checkbadconnections=TRUE
Width [All] p1: maxlimit=100 minlimit=6 preferedwidth=10 checkconnectedcopper=TRUE
13 further rules are at their usual default settings.

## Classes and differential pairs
component class SH5: C89 C90 C91 C92 C94 C95 C96 C101 C102 C103 D13 J42 J43 R87 R88 R89 R100 R102 R109 U2 U3 U6 U7 U8 U9
component class SH4: C81 C82 C83 C84 C86 C87 C88 C93 C97 C106 D9 D10 D11 D12 J33 J36 R73 R74 R75 R76 R77 R78 R79 R80 R81 R83 R84 R85 R86 R90 R91 R92 R110 TP1 TP2 TP3 TP4 U4
component class SH2: C40 C41 C42 C43 C44 C45 C46 C47 C48 C49 C62 C65 C72 C73 C74 C76 C77 C78 C79 C80 D4 D6 D7 J38 J39 J40 J41 L3 L4 L5 NT2 Q8 Q9 R51 R52 R53 R54 R60 R61 R62 R63 R65 R66 R67 R68 R69 R70 R71 R72 R104 R107 TP5 TP6 U5
component class SH7: C85 C98 C99 C100 CS1A CS1B CS2A CS2B D5 J13 J16 J17 J18 J19 J20 J22 J23 J25 J28 J29 J30 J31 J32 J44 R42 R82 R93 R94 R95 R96 R97 R98 R99 R101 R103 R105
component class SH6: C18 C19 C20 C21 C22 C23 C24 C25 C26 C27 C28 C29 C31 C32 C33 C50 C51 C52 C53 C54 C55 C56 C57 C58 C59 C60 C61 C63 C64 C66 C67 C68 C69 C70 C71 C104 C105 J8 J9 J10 J11 L1 L2 Q1 Q2 Q3 Q4 Q10 Q11 Q12 Q13 R21 R22 R23 R24 R25 R26 R27 R28 R29 R30 R32 R33 R34 R35 R36 R37 R38 R39 R40 R41 R56 R57 R58 R59 T1 T2 T3 T4
component class SH3: C1 C2 C3 C4 C5 C6 C7 C8 C9 C10 C11 C12 C13 C14 C15 C16 C17 C30 C34 C35 C36 C37 C38 C39 C75 C107 D1 D2 D3 D8 J1 J2 J3 J4 J5 J6 J7 J12 J14 J15 J21 J24 J26 J27 J34 J35 J37 NT1 Q5 Q6 Q7 R1 R2 R3 R4 R5 R6 R7 R8 R9 R10 R11 R12 R13 R14 R15 R16 R17 R18 R19 R20 R31 R43 R44 R45 R46 R47 R48 R49 R50 R55 R64 R106 R108 U1
component class Header: J1 J2 J3 J4 J5 J6 J7 J12 J13 J14 J15 J16 J17 J18 J19 J20 J21 J22 J23 J24 J25 J26 J27 J28 J29 J30 J32 J33 J34 J35 J36 J37 J38 J39 J40 J41 J42 J43 J44
component class AssemblyNote: ZZ1 ZZ2 ZZ3 ZZ4 ZZ5 ZZ6 ZZ7 ZZ8 ZZ9 ZZ11 ZZ12 ZZ13 ZZ14 ZZ15 ZZ16 ZZ17 ZZ18 ZZ19
component class FiducialMark: FID1 FID2 FID3 FID4 FID5 FID6
component class SH8: FID1 FID2 FID3 FID4 FID5 FID6 H1 H2 H3 H4 H5 H6 H7 H8 Logo5 Logo6 SH-J1 SH-J2 SH-J3 SH-J4 SH-J5 SH-J6 SH-J7 SH-J8 SH-J9 SH-J10 SH-J11 SH-J12 SH-J13 SH-J14 SH-J15 ZZ1 ZZ2 ZZ3 ZZ4 ZZ5 ZZ6 ZZ7 ZZ8 ZZ9 ZZ11 ZZ12 ZZ13 ZZ14 ZZ15 ZZ16 ZZ17 ZZ18 ZZ19
component class "Mounting Holes": H1 H2 H3 H4

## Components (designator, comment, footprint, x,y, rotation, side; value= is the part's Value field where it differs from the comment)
C1 "C0603C102J5RACAUTO" 0603L 2989.24,3408.81 r180 top value=1000pF
C2 "06031C103KAT2A" 0603L 2315,3795 r180 bottom value=0.01uF
C3 "C0603C102J5RACAUTO" 0603L 2427.44,3405 r0 bottom value=1000pF
C4 "C2012X7S2A105K125AB" 0805L 1950,4735 r180 top value=1uF
C5 "GRM188R72A104KA35D" 0603L 2500,3385 r90 bottom value=0.1uF
C6 "C2012X7S2A105K125AB" 0805L 3175,3240 r0 bottom value=1uF
C7 "06031C103KAT2A" 0603L 2495,3485 r270 bottom value=0.01uF
C8 "C0603C101J5GACTU" 0603L 2423.35,3515 r180 bottom value=100pF
C9 "C0603C101J5GACTU" 0603L 2422.44,3460.49 r180 bottom value=100pF
C10 "06031C103KAT2A" 0603L 3810,3820 r270 top value=0.01uF
C11 "C1608X7R1H224K080AB" 0603L 2678.98,3195.13 r270 bottom value=0.22uF
C12 "GRM188R72A104KA35D" 0603L 3085,3790 r90 bottom value=0.1uF
C13 "C2012X7R1C225K125AB" 0805L 2799.71,3134.41 r0 bottom value=2.2uF
C14 "GRM188R72A104KA35D" 0603L 4105,4225 r270 top value=0.1uF
C15 "GRM188R72A104KA35D" 0603L 3170,3305 r0 bottom value=0.1uF
C16 "C0603C102J5RACAUTO" 0603L 2619.05,3391.81 r0 top value=1000pF
C17 "C1608X7R1H224K080AB" 0603L 2936.97,3206.23 r270 bottom value=0.22uF
C18 "EMVH101GDA101MLH0S" CAPSMT_62_LH0 470,3220 r90 top value=100uF
C19 "08051A101KAT2A" 0805L 2155,1785 r270 top value=100pF
C20 "PCR1H181MCL1GS" CR_1000x1270 2785,2675 r90 bottom value=180uF
C21 "PCR1H181MCL1GS" CR_1000x1270 2790,375 r270 bottom value=180uF
C22 "C5750X7R2A475M230KA" 2220_280 735,1650 r0 top value=4.7uF
C23 "C5750X7R2A475M230KA" 2220_280 735,1400 r0 top value=4.7uF
C24 "C5750X7R2A475M230KA" 2220_280 4870,1395 r180 top value=4.7uF
C25 "C5750X7R2A475M230KA" 2220_280 4870,1650 r180 top value=4.7uF
C26 "C5750X7R2A475M230KA" 2220_280 4845,2980 r180 bottom value=4.7uF
C27 "C5750X7R2A475M230KA" 2220_280 755,2995 r0 bottom value=4.7uF
C28 "C5750X7R2A475M230KA" 2220_280 2265,1345 r180 top value=4.7uF
C29 "C5750X7R2A475M230KA" 2220_280 2265,1585 r180 top value=4.7uF
C30 "C0603C101J5GACTU" 0603L 3192.56,3470 r0 bottom value=100pF
C31 "GRM31CR72A105KA01L" 1206_180 3096.33,2773.42 r270 top value=1uF
C32 "EMVH101GDA101MLH0S" CAPSMT_62_LH0 5130,3223 r90 top value=100uF
C33 "08051A101KAT2A" 0805L 3500,1780 r270 top value=100pF
C34 "C0603C101J5GACTU" 0603L 3195,3525 r0 bottom value=100pF
C35 "C0603C102J5RACAUTO" 0603L 3215,3415 r180 bottom value=1000pF
C36 "06031C103KAT2A" 0603L 3120,3490 r90 bottom value=0.01uF
C37 "GRM188R72A104KA35D" 0603L 3125,3390 r270 bottom value=0.1uF
C38 "C0603C101J5GACTU" 0603L 2435,3625 r180 bottom value=100pF
C39 "C0603C101J5GACTU" 0603L 2974.98,3788.5 r90 bottom value=100pF
C40 "GCJ188R72A104KA01D" 0603L 5235,5070 r0 top value=0.1uF
C41 "GRM188R72A222KA01D" 0603L 4680,5390 r270 bottom value=2200pF
C42 "GRM188R72A103KA01D" 0603L 5090,5230 r270 top value=0.01uF
C43 "GRM188R72A103KA01D" 0603L 5150,5230 r270 top value=0.01uF
C44 "C3216X7S2A225K160AB" 1206_180 5225,5340 r90 top value=2.2uF
C45 "C3216X7S2A225K160AB" 1206_180 5315,5340 r90 top value=2.2uF
C46 "C3216X7S2A225K160AB" 1206_180 4840,5225 r180 top value=2.2uF
C47 "C3216X7S2A225K160AB" 1206_180 4840,5135 r180 top value=2.2uF
C48 "C0805C475K3PACTU" 0805L 4640,5030 r180 top value=4.7uF
C49 "C0805C475K3PACTU" 0805L 4640,4835 r180 top value=4.7uF
C50 "HHXA800ARA390MJA0G" HXA_JA0 700,970 r270 top value=39uF
C51 "HHXA800ARA390MJA0G" HXA_JA0 255,970 r270 top value=39uF
C52 "HHXA800ARA390MJA0G" HXA_JA0 4897.31,972.72 r270 top value=39uF
C53 "HHXA800ARA390MJA0G" HXA_JA0 5342.69,972.72 r270 top value=39uF
C54 "PCR1H181MCL1GS" CR_1000x1270 2790,375 r270 top value=180uF
C55 "PCR1H181MCL1GS" CR_1000x1270 2785,2675 r90 top value=180uF
C56 "HHXA800ARA390MJA0G" HXA_JA0 700,970 r270 bottom value=39uF
C57 "HHXA800ARA390MJA0G" HXA_JA0 255,970 r270 bottom value=39uF
C58 "HHXA800ARA390MJA0G" HXA_JA0 340,3135 r90 bottom value=39uF
C59 "HHXA800ARA390MJA0G" HXA_JA0 5260,3135 r90 bottom value=39uF
C60 "HHXA800ARA390MJA0G" HXA_JA0 5342.69,972.72 r270 bottom value=39uF
C61 "HHXA800ARA390MJA0G" HXA_JA0 4897.31,972.72 r270 bottom value=39uF
C62 "GRM155R71H103KA88D" 0402L 4635,4970 r0 top value=0.01uF
C63 "C5750X7R2A475M230KA" 2220_280 4870,1395 r180 bottom value=4.7uF
C64 "C5750X7R2A475M230KA" 2220_280 4870,1650 r180 bottom value=4.7uF
C65 "GRM155R71H103KA88D" 0402L 4635,4920 r0 top value=0.01uF
C66 "C5750X7R2A475M230KA" 2220_280 735,1400 r0 bottom value=4.7uF
C67 "C5750X7R2A475M230KA" 2220_280 735,1650 r0 bottom value=4.7uF
C68 "C5750X7R2A475M230KA" 2220_280 3405,1345 r0 top value=4.7uF
C69 "C5750X7R2A475M230KA" 2220_280 2265,1340 r180 bottom value=4.7uF
C70 "C5750X7R2A475M230KA" 2220_280 2265,1585 r180 bottom value=4.7uF
C71 "C5750X7R2A475M230KA" 2220_280 3405,1585 r0 bottom value=4.7uF
C72 "GRM155R71H103KA88D" 0402L 4640,4775 r0 top value=0.01uF
C73 "C0603C101F5GACTU" 0603L 5015,4810 r180 top value=100pF
C74 "CGA3E1X7R1C105K080AC" 0603L 5110,5025 r0 top value=1uF
C75 "GRM188R72A104KA35D" 0603L 3090,3615 r0 bottom value=0.1uF
C76 "C0603C101F5GACTU" 0603L 5425,5090 r0 top value=100pF
C77 "CGA3E3X7R1H224K080AB" 0603L 5425,4920 r0 top value=0.22uF
C78 "CGA3E2X7R1H683K080AA" 0603L 5110,4820 r270 top value=0.068uF
C79 "C0603C102J5RACAUTO" 0603L 5185,4845 r0 top value=1000pF
C80 "C2012X7R1C225K125AB" 0805L 4885,4525 r270 top value=2.2uF
C81 "C0603C101J5GACTU" 0603L 2455,4280 r270 top value=100pF
C82 "C0603C101J5GACTU" 0603L 3075,4280 r90 top value=100pF
C83 "C0603C101J5GACTU" 0603L 2670,4200 r180 top value=100pF
C84 "C0603C101J5GACTU" 0603L 2865,4200 r180 top value=100pF
C85 "06031C103KAT2A" 0603L 2210,3485 r90 top value=0.01uF
C86 "CGA3E3X7S2A333K080AB" 0603L 2695,4280 r90 top value=0.033uF
C87 "06031C103KAT2A" 0603L 2840,4280 r90 top value=0.01uF
C88 "GRM188R72A104KA35D" 0603L 3700,4075 r270 top value=0.1uF
C89 "GRM188R72A104KA35D" 0603L 130,2315 r270 bottom value=0.1uF
C90 "GRM188R72A104KA35D" 0603L 4080,4000 r180 top value=0.1uF
C91 "GRM188R72A104KA35D" 0603L 1654.93,4366.15 r90 top value=0.1uF
C92 "GRM188R72A104KA35D" 0603L 1560,2230 r270 bottom value=0.1uF
C93 "GRM188R72A104KA35D" 0603L 1178.98,3586.81 r180 top value=0.1uF
C94 "GRM188R72A104KA35D" 0603L 1501.3,4511.54 r180 top value=0.1uF
C95 "C0603C101J5GACTU" 0603L 4137.56,4055 r180 top value=100pF
C96 "C0603C101J5GACTU" 0603L 1345,4370 r90 top value=100pF
C97 "GRM188R72A104KA35D" 0603L 3645,4075 r270 top value=0.1uF
C98 "06031C103KAT2A" 0603L 3435,3480 r90 top value=0.01uF
C99 "06031C103KAT2A" 0603L 2265,3485 r90 top value=0.01uF
C100 "06031C103KAT2A" 0603L 3375,3480 r90 top value=0.01uF
C101 "GRM188R72A104KA35D" 0603L 5460,2260 r90 bottom value=0.1uF
C102 "C0603C101J5GACTU" 0603L 1870,3980 r270 top value=100pF
C103 "GRM188R72A104KA35D" 0603L 4265,2235 r270 bottom value=0.1uF
C104 "C5750X7R2A475M230KA" 2220_280 3402.64,1585 r0 top value=4.7uF
C105 "C5750X7R2A475M230KA" 2220_280 3405,1345 r0 bottom value=4.7uF
C106 "C0603C101J5GACTU" 0603L 3250,4120.04 r270 bottom value=100pF
C107 "C2012X7R1C225K125AB" 0805L 2794.64,3119.1 r90 top value=2.2uF
CS1A "S2751-46R" Harwin_S2751-46R 2120,3575 r180 top
CS1B "S2751-46R" Harwin_S2751-46R 2121.23,3396.23 r180 top
CS2A "S2751-46R" Harwin_S2751-46R 3519.9,3595.1 r0 top
CS2B "S2751-46R" Harwin_S2751-46R 3515,3390 r0 top
D1 "PMEG10010ELRX" SOD-123W 2695,3035 r0 bottom value=100V
D2 "PMEG10010ELRX" SOD-123W 2905,3035 r180 bottom value=100V
D3 "1N4148X-TP" SOD-523 1775,4005 r180 top value=75V
D4 "PDS5100HQ-13" POWERDI5 4605,5175 r180 top value=100V
D5 "150060SS75000" WL-SMCW_RED 1945,4035 r90 top value="Super Red"
D6 "B230A-13-F" SMA 4650,4545 r180 top value=30V
D7 "B230A-13-F" SMA 5354.24,3961.87 r0 top value=30V
D8 "MM3Z4V7ST1G" SOD-323 3235,3883.19 r180 bottom value=4.7V
D9 "1N4448WX-TP" SOD-323 2685,4100 r90 top value=75V
D10 "1N4448WX-TP" SOD-323 2840,4100.41 r90 top value=75V
D11 "150060VS75000" WL-SMCW_GREEN 696.77,4022.12 r270 top value=Green
D12 "150060YS75000" WL-SMCW_YELLOW 698.23,4498.7 r270 top value=Yellow
D13 "1N4448WX-TP" SOD-323 4147.71,3792.44 r180 top value=75V
FID1 "Fiducial" Fiducial10-20 500,100 r0 top
FID2 "Fiducial" Fiducial10-20 5100,100 r0 top
FID3 "Fiducial" Fiducial10-20 500,6000 r0 top
FID4 "Fiducial" Fiducial10-20 500,100 r180 bottom
FID5 "Fiducial" Fiducial10-20 5100,100 r180 bottom
FID6 "Fiducial" Fiducial10-20 500,6000 r180 bottom
H1 "NY PMS 440 0025 PH" "NY PMS 440 0025 PH" 300,300 r0 top
H2 "NY PMS 440 0025 PH" "NY PMS 440 0025 PH" 5300,300 r0 top
H3 "NY PMS 440 0025 PH" "NY PMS 440 0025 PH" 300,5800 r0 top
H4 "NY PMS 440 0025 PH" "NY PMS 440 0025 PH" 5300,5800 r0 top
H5 "1902C" Keystone_1902C 300,300 r180 bottom
H6 "1902C" Keystone_1902C 5300,300 r180 bottom
H7 "1902C" Keystone_1902C 300,5800 r180 bottom
H8 "1902C" Keystone_1902C 5300,5800 r180 bottom
J1 "61300311121" WURTH_61300311121 3750,3550 r180 top
J2 "61300211121" WURTH_61300211121 2195,3950 r0 top
J3 "61300211121" WURTH_61300211121 1900,4350 r0 top
J4 "61300211121" WURTH_61300211121 1395,4050 r270 top
J5 "61300211121" WURTH_61300211121 4300,4300 r90 top
J6 "61300311121" WURTH_61300311121 3300,4350 r180 top
J7 "61300211121" WURTH_61300211121 3700,3950 r0 top
J8 "6095" FP-6095_CONN_JACK-MFG 1250,500 r90 top
J9 "6095" FP-6095_CONN_JACK-MFG 3625,500 r90 top
J10 "6095" FP-6095_CONN_JACK-MFG 2000,500 r90 top
J11 "6095" FP-6095_CONN_JACK-MFG 4375,500 r90 top
J12 "61300211121" WURTH_61300211121 3995,4360 r180 top
J13 "61300311121" WURTH_61300311121 3350,5300 r90 top
J14 "61300211121" WURTH_61300211121 3050,5300 r90 top
J15 "61300211121" WURTH_61300211121 2900,5305 r90 top
J16 "61300211121" WURTH_61300211121 2445,3950 r0 top
J17 "HMTSW-130-07-G-D-240" SAMTEC_HMTSW-130-07-G-D-240 2700,4900 r270 top locked
J18 "HMTSW-130-07-G-D-240" SAMTEC_HMTSW-130-07-G-D-240 2700,5700 r270 top locked
J19 "61300211121" WURTH_61300211121 2050,5300 r270 top
J20 "61300211121" WURTH_61300211121 1900,5300 r270 top
J21 "61300211121" WURTH_61300211121 3400,3950 r0 top
J22 "61300211121" WURTH_61300211121 3950,5250 r90 top
J23 "61300211121" WURTH_61300211121 3800,5250 r90 top
J24 "61300211121" WURTH_61300211121 3700,4355 r180 top
J25 "61300211121" WURTH_61300211121 1076.4,5230.37 r90 top
J26 "61300311121" WURTH_61300311121 1650,4005 r90 top
J27 "61300211121" WURTH_61300211121 2300,4350 r0 top
J28 "61300311121" WURTH_61300311121 3650,5300 r90 top
J29 "61300311121" WURTH_61300311121 3500,5300 r90 top
J30 "61300311121" WURTH_61300311121 3200,5300 r90 top
J31 "N2510-6002-RB" CONN_2510-6002 652.36,5032.48 r90 top
J32 "61300211121" WURTH_61300211121 2745,5350 r90 top
J33 "61300211121" WURTH_61300211121 3905,4150 r0 top
J34 "61300311121" WURTH_61300311121 1900,3650 r90 top
J35 "61300311121" WURTH_61300311121 1655,3655 r270 top
J36 "61300311121" WURTH_61300311121 3445,4150 r0 top
J37 "61300211121" WURTH_61300211121 2993.56,4023.3 r180 top
J38 "61300211121" WURTH_61300211121 4605,4680 r180 top
J39 "61300211121" WURTH_61300211121 4626.22,4388.89 r0 top
J40 "61300211121" WURTH_61300211121 3390,3700 r0 top
J41 "61300211121" WURTH_61300211121 5435,4147.06 r270 top
J42 "61300211121" WURTH_61300211121 4055,3690 r180 top
J43 "61300211121" WURTH_61300211121 4400,3945 r180 top
J44 "61300211121" WURTH_61300211121 946.3,5228.58 r90 top
L1 "74436410470" WE-HCF_2818 1540,2960 r90 top value=4.7uH
L2 "74436410470" WE-HCF_2818 4050,2950 r90 top value=4.7uH
L3 "XGL6060-223MEC" FP-XGL6060-223MEC_SMT2_6MM51_6MM71-MFG 5020,5430 r180 top value=22uH
L4 "XGL6060-223MEC" FP-XGL6060-223MEC_SMT2_6MM51_6MM71-MFG 4730,5430 r0 top value=22uH
L5 "BLM18SG121TN1D" 0603 4550,4880 r90 top value="120 ohm"
Logo5 "CAUTION HOT SURFACE" IEC_HotSurface_Small 1068.21,2400.66 r0 top
Logo6 "CAUTION HOT SURFACE" IEC_HotSurface_Small 4528.58,2385.45 r0 top
NT1 "Net-Tie" Net-Tie_10mil 2820,3340 r270 bottom net-tie
NT2 "Net-Tie" Net-Tie_10mil 5255,4875 r270 top net-tie
Q1 "IPB042N10N3GATMA1" FP-IPB042N10N3GATMA1_D2PAK-MFG 614.27,2030 r90 top
Q2 "IPB042N10N3GATMA1" FP-IPB042N10N3GATMA1_D2PAK-MFG 1200,1860 r0 top
Q3 "IPB042N10N3GATMA1" FP-IPB042N10N3GATMA1_D2PAK-MFG 1705,1860 r0 top
Q4 "IPB042N10N3GATMA1" FP-IPB042N10N3GATMA1_D2PAK-MFG 614.27,2530 r90 top
Q5 "2N7002E-T1-E3" SOT-23 1145,4145 r180 top value=60V
Q6 "2N7002E-T1-E3" SOT-23 1240,4000 r0 top value=60V
Q7 "2N7002E-T1-E3" SOT-23 1950,4545 r270 top value=60V
Q8 "IAUZ30N10S5L240ATMA1" FP-IAUZ30N10S5L240ATMA1_TDSON8-MFG 4930,4995 r0 top
Q9 "PMT560ENEAX" FP-PMT560ENEAX_SOT223-MFG 5140,4225 r270 top
Q10 "IPB042N10N3GATMA1" FP-IPB042N10N3GATMA1_D2PAK-MFG 5020,2030 r270 top
Q11 "IPB042N10N3GATMA1" FP-IPB042N10N3GATMA1_D2PAK-MFG 4415,1860 r0 top
Q12 "IPB042N10N3GATMA1" FP-IPB042N10N3GATMA1_D2PAK-MFG 3915,1860 r0 top
Q13 "IPB042N10N3GATMA1" FP-IPB042N10N3GATMA1_D2PAK-MFG 5020,2525 r270 top
R1 "CRCW060361K9FKEA" 0603L 4180,4345 r180 top value=61.9k
R2 "CRCW0805100KFKEA" 0805L 3425,3820 r0 bottom value=100k
R3 "CRCW060310K0FKEA" 0603L 2315,3850 r180 bottom value=10.0k
R4 "RC0603FR-073K65L" 0603L 2430.17,3351.55 r180 bottom value=3.65k
R5 "CRCW060349K9FKEA" 0603L 1950,4665 r0 top value=49.9k
R6 "CRCW060349K9FKEA" 0603L 3310,3820 r0 bottom value=49.9k
R7 "CRCW060320K0FKEA" 0603L 2865,3790 r90 bottom value=20.0k
R8 "CRCW060361K9FKEA" 0603L 1520,3905 r0 top value=61.9k
R9 "CRCW060320K0FKEA" 0603S 2920,3790 r270 bottom value=20.0k
R10 "CRCW06031K00FKEA" 0603L 1950,4230 r270 top value=1.00k
R11 "CRCW060330K1FKEA" 0603L 3017.44,3695.22 r270 top value=30.1k
R12 "CRCW060349K9FKEA" 0603L 1120,4000 r90 top value=49.9k
R13 "CRCW08052R00JNEA" 0805L 2613.98,3150.13 r270 bottom value=2.0
R14 "CRCW060310K0FKEA" 0603L 3027.35,3790 r270 bottom value=10.0k
R15 "CRCW060349K9FKEA" 0603L 3205,4015 r270 top value=49.9k
R16 "CRCW060338K3FKEA" 0603L 2790,3790 r270 bottom value=38.3k
R17 "CRCW060310K0FKEA" 0603L 2135,4350 r180 top value=10.0k
R18 "CRCW060310K0FKEA" 0603L 4020,4255 r0 top value=10.0k
R19 "CRCW08052R00JNEA" 0805L 2999.78,3154.09 r270 bottom value=2.0
R20 "CRCW0603750KFKEA" 0603L 2865,3928.94 r0 bottom value=750k
R21 "FC4L90R001GER" FP-FC4L90R001GER_1835-MFG 2330,2500 r0 top value=1m
R22 "CRCW08051R00FKEA" 0805L 820,2055 r270 bottom value=1.00
R23 "CRCW121810R0FKEK" 1218 2100,1960 r180 top value=10.0
R24 "CRCW080549K9FKEA" 0805L 1170,1610 r0 bottom value=49.9k
R25 "CRCW080549K9FKEA" 0805L 1670,1610 r0 bottom value=49.9k
R26 "CRCW080549K9FKEA" 0805L 842.71,1938.51 r180 bottom value=49.9k
R27 "CRCW08051R00FKEA" 0805L 1135,1740 r270 bottom value=1.00
R28 "CRCW08051R00FKEA" 0805L 1631.77,1740 r270 bottom value=1.00
R29 "CRCW080549K9FKEA" 0805L 820,2550 r270 bottom value=49.9k
R30 "CRCW08051R00FKEA" 0805L 780,2430 r0 bottom value=1.00
R31 "CRCW060310K0FKEA" 0603L 3750,3820 r90 top value=10.0k
R32 "FC4L90R001GER" FP-FC4L90R001GER_1835-MFG 3261.18,2500 r0 top value=1m
R33 "CRCW080549K9FKEA" 0805L 4793.19,2241.02 r90 bottom value=49.9k
R34 "CRCW121810R0FKEK" 1218 3555,1950 r0 top value=10.0
R35 "CRCW080549K9FKEA" 0805L 4360,1620 r0 bottom value=49.9k
R36 "CRCW080549K9FKEA" 0805L 3860,1620 r0 bottom value=49.9k
R37 "CRCW08051R00FKEA" 0805L 4825,2145 r180 bottom value=1.00
R38 "CRCW08051R00FKEA" 0805L 4320,1740 r270 bottom value=1.00
R39 "CRCW08051R00FKEA" 0805L 3820,1740 r270 bottom value=1.00
R40 "CRCW080549K9FKEA" 0805L 4730.67,2706.83 r90 bottom value=49.9k
R41 "CRCW08051R00FKEA" 0805L 4825,2632.44 r180 bottom value=1.00
R42 "CRCW06033K24FKEA" 0603L 1845,4110 r180 top value=3.24k
R43 "RC0603FR-073K65L" 0603L 3215,3360 r180 bottom value=3.65k
R44 "ERJ-3GEY0R00V" 0603L 1780,3550 r0 top value=0
R45 "CRCW060323K2FKEA" 0603L 2055,4710 r90 top value=23.2k
R46 "CRCW060315K0FKEA" 0603L 3115,3695 r90 bottom value=15.0k
R47 "CRCW0603316RFKEA" 0603L 1530,3755 r0 top value=316
R48 "CRCW060360K4FKEA" 0603L 1530,3555 r0 top value=60.4k
R49 "CRCW06031K00FKEA" 0603L 2435,3570 r0 bottom value=1.00k
R50 "CRCW060320K0FKEA" 0603L 3140,3790 r270 bottom value=20.0k
R51 "ERJ-14BQF2R0U" 1210 4590,5360 r270 bottom value=2.00
R52 "RC0603JR-070RL" 0603L 5110,4970 r0 top value=0
R53 "RC0603JR-070RL" 0603L 5110,4915 r0 top value=0
R54 "RC0603FR-07100RL" 0603L 5015,4865 r0 top value=100
R55 "CRCW060395K3FKEA" 0603L 1775,3750 r0 top value=95.3k
R56 "CRCW06031R00FKEA" 0603L 2445,3510 r180 top value=1.00
R57 "CRCW06031R00FKEA" 0603L 2450,3455 r180 top value=1.00
R58 "CRCW06031R00FKEA" 0603L 3167.56,3515 r0 top value=1.00
R59 "CRCW06031R00FKEA" 0603L 3167.56,3460 r0 top value=1.00
R60 "PRL1632-R030-F-T1" 0612 4875,4830 r90 top value=0.03
R61 "CRCW080510R0JNEA" 0805L 5235,5155 r0 bottom value=10
R62 "CRCW0603100RFKEA" 0603L 3555,3700 r180 top value=100
R63 "CRCW0603100RFKEA" 0603L 5395,4563.19 r270 bottom value=100
R64 "CRCW060310K0FKEA" 0603S 3194.78,3791.81 r270 bottom value=10.0k
R65 "RC0603FR-0749K9L" 0603L 5395,4765 r270 bottom value=49.9k
R66 "CRCW06035K23FKEA" 0603L 5425,4865 r180 top value=5.23k
R67 "RC0603FR-0749K9L" 0603L 5425,4975 r180 top value=49.9k
R68 "RCL06125R11FKEA" FP-RCL06125R11FKEA_0612-MFG 5045,4520 r270 top value=5.11
R69 "CRCW0603100KFKEA" 0603L 5425,5143 r180 top value=100k
R70 "CRCW06032K49FKEA" 0603L 5185,4790 r180 top value=2.49k
R71 "RC0603FR-07100RL" 0603L 5350,4340 r0 top value=100
R72 "RC0603FR-0749K9L" 0603L 5175,4435 r0 top value=49.9k
R73 "CRCW060320K0FKEA" 0603L 2515,4280 r90 top value=20.0k
R74 "CRCW060320K0FKEA" 0603L 3010,4280 r270 top value=20.0k
R75 "CRCW080549K9FKEA" 0805L 2485,4190 r180 top value=49.9k
R76 "CRCW080526K7FKEA" 0805L 3040,4185 r180 top value=26.7k
R77 "CRCW0603100RFKEA" 0603L 2360,4185 r180 top value=100
R78 "CRCW0603100RFKEA" 0603L 3152.2,4173.34 r180 top value=100
R79 "CRCW06032K10FKEA" 0603L 2575,4277.56 r90 top value=2.10k
R80 "CRCW06034K42FKEA" 0603L 2950,4282.44 r90 top value=4.42k
R81 "CRCW06031K00FKEA" 0603L 2765,4090 r270 top value=1.00k
R82 "CRCW060310K0FKEA" 0603L 2235,3555 r180 top value=10.0k
R83 "RC0603FR-0775KL" 0603L 2635,4280 r270 top value=75.0k
R84 "CRCW060324K9FKEA" 0603L 2895,4280 r270 top value=24.9k
R85 "CRCW06031K00FKEA" 0603L 3670,4150 r180 top value=1.00k
R86 "CRCW06034K02FKEA" 0603L 2765,4280 r270 top value=4.02k
R87 "CRCW06031K00JNEA" 0603L 4200,3990 r0 top value=1.0k
R88 "CRCW0805100KFKEA" 0805L 1400,4245 r270 top value=100k
R89 "CRCW060315K0FKEA" 0603L 1730.38,4338.3 r180 top value=15.0k
R90 "CRCW06034K99FKEA" 0603L 1070.47,3589.16 r180 top value=4.99k
R91 "CRCW06034K99FKEA" 0603L 1146.22,3878.94 r90 top value=4.99k
R92 "CRCW06031K00FKEA" 0603L 3755,4125 r90 top value=1.00k
R93 "CRCW060310K0FKEA" 0603L 2235,3415 r180 top value=10.0k
R94 "CRCW060310K0FKEA" 0603L 3405,3550 r0 top value=10.0k
R95 "CRCW060310K0FKEA" 0603L 3405,3410 r0 top value=10.0k
R96 "CRCW060310K0FKEA" 0603L 2355,3555 r180 top value=10.0k
R97 "CRCW060310K0FKEA" 0603L 2355,3415 r180 top value=10.0k
R98 "CRCW060310K0FKEA" 0603L 3295,3545 r0 top value=10.0k
R99 "CRCW060310K0FKEA" 0603L 3290,3430 r0 top value=10.0k
R100 "CRCW06032K74FKEA" 0603L 1400,4370 r270 top value=2.74k
R101 "CRCW06034K99FKEAC" 0603 1075.28,5053.9 r270 top value=4.99k
R102 "CRCW0402100KFKED" 0402L 1845,4060 r180 top value=100k
R103 "CRCW06034K99FKEAC" 0603 947.45,5052.09 r270 top value=4.99k
R104 "RC0603JR-070RL" 0603L 5425,4810 r0 top value=0
R105 "RC0603FR-071KL" 0603 3019.98,5160.84 r180 bottom value=1.00k
R106 "ERJ-3GEY0R00V" 0603L 2809.97,3347.13 r90 top value=0
R107 "RC0603JR-070RL" 0603L 5134.09,5095.63 r90 top value=0
R108 "CRCW060320K0FKEA" 0603S 1730,4215.14 r0 top value=20.0k
R109 "CRCW060320K0FKEA" 0603L 1601.63,4366.15 r270 top value=20.0k
R110 "CRCW080510R0JNEA" 0805_HV1 1007.92,3800 r180 top value=10
SH-J1 "M7582-05" Harwin_M7582-05 2202.15,3950 r180 top
SH-J2 "M7582-05" Harwin_M7582-05 1395,4042.85 r90 top
SH-J3 "M7582-05" Harwin_M7582-05 4300,4307.15 r90 top
SH-J4 "M7582-05" Harwin_M7582-05 3695.35,3955.51 r180 top
SH-J5 "M7582-05" Harwin_M7582-05 2900,5302.57 r90 top
SH-J6 "M7582-05" Harwin_M7582-05 3700,4364.86 r180 top
SH-J7 "M7582-05" Harwin_M7582-05 3402.15,4150 r180 top
SH-J8 "M7582-05" Harwin_M7582-05 4612.29,4684.35 r180 top
SH-J9 "M7582-05" Harwin_M7582-05 3397.15,3700 r180 top
SH-J10 "M7582-05" Harwin_M7582-05 5435,4139.9 r90 top
SH-J11 "M7582-05" Harwin_M7582-05 3792.85,3550 r180 top
SH-J12 "M7582-05" Harwin_M7582-05 3257.15,4350 r180 top
SH-J13 "M7582-05" Harwin_M7582-05 3650,5257.15 r90 top
SH-J14 "M7582-05" Harwin_M7582-05 3500,5257.15 r90 top
SH-J15 "M7582-05" Harwin_M7582-05 1900,3607.15 r90 top
T1 "CXS70-14-C" Panduit_CXS70-14-C 1250,500 r90 top
T2 "CXS70-14-C" Panduit_CXS70-14-C 3625,500 r90 top
T3 "CXS70-14-C" Panduit_CXS70-14-C 2000,500 r90 top
T4 "CXS70-14-C" Panduit_CXS70-14-C 4375,500 r90 top
TP1 "S2761-46R" Harwin_S2761-46R 2252.8,4184.57 r0 top
TP2 "S2761-46R" Harwin_S2761-46R 2406.59,4083.27 r0 top
TP3 "S2761-46R" Harwin_S2761-46R 3126.23,4240.15 r270 top
TP4 "S2761-46R" Harwin_S2761-46R 3231.87,4190.75 r90 top
TP5 "TESTPOINT" TESTPOINT 5290,4486.71 r0 top
TP6 "TESTPOINT" TESTPOINT 5290,4622 r0 top
U1 "LM5171PHP" PHP0048E-MFG 2810,3470 r180 bottom
U2 "OPA320AQDBVRQ1" DBV0005A_N 4115,3897.29 r180 top
U3 "TL331BQDBVRQ1" DBV0005A-MFG 1510,4390 r90 top
U4 "SN74LVC1G04QDBVRQ1" DBV0005A_N 1205,3685 r180 top
U5 "LM5156DSSR" DSS0012B 5262.4,4960.16 r0 top
U6 "LM26LV" NGF0006A 1459.72,2244.41 r0 bottom
U7 "LM26LV" NGF0006A 5362.34,2277.72 r270 bottom
U8 "LM26LV" NGF0006A 4165,2245 r0 bottom
U9 "LM26LV" NGF0006A 225,2285 r90 bottom
ZZ1 "These assemblies are ESD sensitive, ESD precautions shall be observed." AssemblyNote 1.97,7980.29 r0 top
ZZ2 "These assemblies must be clean and free from flux and all contaminants. Use of no clean flux is not acceptable." AssemblyNote 1.97,7877.68 r0 top
ZZ3 "These assemblies must comply with workmanship standards IPC-A-610 Class 2, unless otherwise specified." AssemblyNote 1.97,7775.07 r0 top
ZZ4 "Install Shunt Jumper SH-J1 onto header J2." AssemblyNote 1.97,7672.46 r0 top
ZZ5 "Install Shunt Jumper SH-J2 onto header J4." AssemblyNote 1.97,7569.84 r0 top
ZZ6 "Install Shunt Jumper SH-J3 onto header J5." AssemblyNote 1.97,7467.23 r0 top
ZZ7 "Install Shunt Jumper SH-J4 onto header J7." AssemblyNote 1.97,7364.62 r0 top
ZZ8 "Install Shunt Jumper SH-J5 onto header J15." AssemblyNote 1.97,7262.01 r0 top
ZZ9 "Install Shunt Jumper SH-J6 onto header J24." AssemblyNote 1.97,7159.39 r0 top
ZZ11 "Install Shunt Jumper SH-J8 onto header J38." AssemblyNote 1.97,7054.17 r0 top
ZZ12 "Install Shunt Jumper SH-J9 onto header J40." AssemblyNote 1.97,6951.56 r0 top
ZZ13 "Install Shunt Jumper SH-J10 onto header J41." AssemblyNote 1.97,6848.94 r0 top
ZZ14 "Install Shunt Jumper SH-J11 onto header J1 pins 1-2." AssemblyNote 1.97,6746.33 r0 top
ZZ15 "Install Shunt Jumper SH-J12 onto header J6 pins 2-3." AssemblyNote 1.97,6643.72 r0 top
ZZ16 "Install Shunt Jumper SH-J13 onto header J28 pins 1-2." AssemblyNote 1.97,6541.11 r0 top
ZZ17 "Install Shunt Jumper SH-J14 onto header J29 pins 1-2." AssemblyNote 1.97,6438.49 r0 top
ZZ18 "Install Shunt Jumper SH-J15 onto header J34 pins 1-2." AssemblyNote 1.97,6335.88 r0 top
ZZ19 "Install Shunt Jumper SH-J7 onto header J36 pins 1-2." AssemblyNote 1.97,6233.27 r0 top

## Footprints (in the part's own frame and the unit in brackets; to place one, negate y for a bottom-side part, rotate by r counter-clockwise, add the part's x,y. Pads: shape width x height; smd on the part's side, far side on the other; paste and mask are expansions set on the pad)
0402L [mm] "0402 from SM-752 data"
  rect 0.6x0.5 smd: 1(-0.5,0) 2(0.5,0)
  body extent -0.55,-0.3 0.55,0.3, height 0.6
0603 [mm] "0603 from SM-752 data"
  rect 1x0.95 smd: 1(-0.8,0) 2(0.8,0)
  silkscreen extent -1.52,-0.69 1.52,0.69, body extent -0.87,-0.47 0.87,0.47, height 1
0603L [mm] "0603 from SM-752 data"
  rect 0.8x0.85 smd: 1(-0.7,0) 2(0.7,0)
  silkscreen extent -0.07,-0.33 0.07,0.33, body extent -0.87,-0.47 0.87,0.47, height 1
0603S [mil]
  rect 20x35 smd: 1(-30,0) 2(30,0)
  body extent -34,-19 34,19, height 39
0612 [mm] "Panasonic recommended land pattern, fb97d03ed01.pdf dated April 2008"
  rect 0.95x3.2 smd: 1(-0.775,0) 2(0.775,0)
  silkscreen extent -1.1,-1.9 1.1,1.9, body extent -0.9,-1.7 0.9,1.7, height 0.85
0805_HV1 [mm] "Custom footprint based on analyzing multiple manufacturer recommendations"
  rrect10% 1x1.25 smd: 1(-1,0) 2(1,0)
  silkscreen extent -0.2,-0.75 0.2,0.75, body extent -1.1,-0.72 1.1,0.73, height 1.45
0805L [mm] "0805 from SM-752 data"
  rect 1.1x1.4 smd: 1(-0.75,0) 2(0.75,0)
  body extent -1.1,-0.72 1.1,0.72, height 1.45
1206_180 [mm] "1206_180"
  rect 1.1x1.6 smd: 1(-1.7,0) 2(1.7,0)
  silkscreen extent -0.9,-1 0.9,1, body extent -1.75,-0.95 1.75,0.95, height 1.8
1210 [mm] "1210 from SM-752 data"
  rect 1.3x2.7 smd: 1(-1.45,0) 2(1.45,0)
  silkscreen extent -2.32,-1.57 2.32,1.57, body extent -1.7,-1.35 1.7,1.35, height 1.35
1218 [mil] "Vishay recommended land pattern for 1218, document number 20008 revision 13-Oct-08"
  rrect10% 40x187 smd: 1(-59,0) 2(59,0)
  body extent -65,-93 65,93, height 24
2220_280 [mm] "Chip Capacitor, Body 5.7x5.0mm, IPC Medium Density"
  rect 1.6x5.3 smd: 1(-2.6,0) 2(2.6,0)
  silkscreen extent -3.69,-2.94 3.69,2.94, body extent -2.95,-2.62 2.95,2.62, height 2.8
AssemblyNote [mil] "Assembly Note"
CAPSMT_62_LH0 [mm] "16 x 16.5mm:  Chemi-Con LH0"
  rect 7.8x9.6 smd: 1(-6.25,0) 2(6.25,0)
  silkscreen extent -8.55,-8.55 8.55,8.55, body extent -8.55,-8.55 8.55,8.55, height 17
CONN_2510-6002 [mm] "3M 2500 series TS-0770-L December 15, 2011"
  rect 1.65x1.65 hole 1.016 mask+0: 1(-5.08,-1.27)
  round 1.65 hole 1.016 mask+0: 2(-5.08,1.27) 3(-2.54,-1.27) 4(-2.54,1.27) 5(0,-1.27) 6(0,1.27) 7(2.54,-1.27) 8(2.54,1.27) 9(5.08,-1.27) 10(5.08,1.27)
  silkscreen extent -10.01,-4.17 10.01,4.47, body extent -10.01,-4.11 10.01,4.52, height 9.92
CR_1000x1270 [mm] "SMD, 2-Leads, Dia 10.5mm, Pin Spacing 8mm"
  rect 4x2 smd: 1(-4,0) 2(4,0)
  silkscreen extent -7.4,-5.25 5.25,5.25, body extent -5.25,-5.25 5.25,5.25, height 12.71
DBV0005A-MFG [mm]
  rrect17% 1.1x0.6 smd paste+0 mask+0: 1(-1.3,0.95) 2(-1.3,0) 3(-1.3,-0.95) 4(1.3,-0.95) 5(1.3,0.95)
  silkscreen extent -2.57,-1.53 0.87,1.53, body extent -1.95,-1.78 1.95,1.78, height 0.25
DBV0005A_N [mm] "SOT23, 5-Leads, Body 2.9x1.6mm, Pitch 0.95mm, Lead Span 2.8mm, IPC Medium Density"
  rrect17% 1x0.6 smd: 1(-1.375,0.95) 2(-1.375,0) 3(-1.375,-0.95) 4(1.375,-0.95) 5(1.375,0.95)
  silkscreen extent -1.63,-1.55 0.38,1.55, body extent -1.42,-1.46 1.42,1.46, height 1.09
DSS0012B [mm] "WSON-10"
  rrect40% 0.5x0.25 smd: 1(-0.95,1.25) 2(-0.95,0.75) 3(-0.95,0.25) 4(-0.95,-0.25) 5(-0.95,-0.75) 6(-0.95,-1.25) 7(0.95,-1.25) 8(0.95,-0.75) 9(0.95,-0.25) 10(0.95,0.25) 11(0.95,0.75) 12(0.95,1.25)
  rrect11% 1x2.65 smd paste-0.5: 13(0,0)
  body extent -1,-1.5 1,1.5, height 0.81
Fiducial10-20 [mm]
  round 1 smd mask+0.5: 1(0,0)
  Top Layer keep-out circle w1.178: c0,0 r0.5
FP-6095_CONN_JACK-MFG [mil]
  round 500 hole 270 paste-39370.1 mask+0: 1(0,0)
  body extent -254,-254 580,254, height 10
FP-FC4L90R001GER_1835-MFG [mm]
  rrect9% 1.4x1.1 smd paste+0 mask+0: 1(-2.1,4.175) 2(2.1,4.175)
  rrect7% 1.4x7.8 smd paste+0 mask+0: 3(-2.1,-0.825) 4(2.1,-0.825)
  silkscreen extent -3.47,-4.65 1.02,4.65, body extent -2.9,-4.82 2.9,4.82, height 0.25
FP-IAUZ30N10S5L240ATMA1_TDSON8-MFG [mm]
  rrect11% 1.64x0.9 smd paste-1000 mask-1000: 1-2-3(-0.325,-1.45)
  rrect29% 0.34x0.9 smd paste-1000 mask+0: 4(0.975,-1.45)
  rrect4% 2.29x2.36 smd paste-1000 mask-1000: 5-6-7-8(0,0.7)
  silkscreen extent -1.7,-2.57 1.7,1.7, body extent -1.8,-2 1.8,1.98, height 0.25
FP-IPB042N10N3GATMA1_D2PAK-MFG [mm] "D2-PAK, 3-Pads, Body 9.7x10.4mm (max), TO-263AB, using Vishay Silionix recommended pad sizes"
  rrect7% 1.35x4.6 smd paste-1000 mask+0: 1(-2.54,-5.775) 3(2.54,-5.775)
  rrect1% 10.8x9.4 smd paste-1000 mask+0: 4(0,3.375)
  silkscreen extent -5.1,-2.73 5.1,-1.7, body extent -5.5,-8.18 5.5,8.18, height 0.25
FP-PMT560ENEAX_SOT223-MFG [mm]
  rrect8% 1.3x1.3 smd paste-1000 mask+0: 1(-3.05,2.3) 2(-3.05,0) 3(-3.05,-2.3)
  rrect8% 1.3x3.6 smd paste-1000 mask+0: 4(3.05,0)
  silkscreen extent -4.37,-3.35 1.85,3.35, body extent -3.83,-3.5 3.83,3.5, height 0.25
FP-RCL06125R11FKEA_0612-MFG [mm]
  rrect10% 1x3.5 smd paste+0 mask+0: 1(-0.8,0) 2(0.8,0)
  silkscreen extent -0.9,-2.12 0.9,2.12, body extent -1.4,-1.85 1.4,1.85, height 0.25
FP-XGL6060-223MEC_SMT2_6MM51_6MM71-MFG [mm]
  rrect7% 1.43x5.5 smd paste+0 mask+0: 1(-2.02,0) 2(2.02,0)
  silkscreen extent -3.95,-3.45 3.35,3.45, body extent -3.45,-3.55 3.45,3.55, height 0.25
Harwin_M7582-05 [mil] "Single Operation 2.54mm Pitch Open Top Jumper Socket"
  body extent -98,-47 98,47, height 236
Harwin_S2751-46R [mm] "Test Point, SMT"
  rect 2.2x1.4 smd: 1(0,0)
  body extent -1,-0.6 1,0.6, height 1.4
Harwin_S2761-46R [mm] "Natural PC Test Point Brass, SMT"
  rrect10% 1.8x1 smd: 1(0,0)
  body extent -0.8,-0.4 0.8,0.4, height 1.15
HXA_JA0 [mm] "SMD, 2-Leads, Dia 10mm"
  rect 4.4x2.2 smd: 1(-4.45,0) 2(4.45,0)
  silkscreen extent -5.25,-5.25 5.25,5.25, body extent -5.55,-5.25 5.55,5.25, height 10.51
IEC_HotSurface_Small [mil]
  silkscreen extent -107,-93 107,92
Keystone_1902C [mil] "Hex Standoff, 4-40 threaded, nylon"
  round 1 on Mech4: 0(0,0)
  body extent -145,-126 146,126, height 501
Net-Tie_10mil [mil] "10mil net tie, no solder mask opening, no solder paste"
  rect 10x10 smd paste-5 mask-5: 1(-10,0) 2(10,0)
  Top Layer region: -6,5 6,5 6,-5 -6,-5
NGF0006A [mm] "TI"
  rect 0.6x0.25 smd: 1(-1.15,0.65) 2(-1.15,0) 3(-1.15,-0.65) 4(1.15,-0.65) 5(1.15,0) 6(1.15,0.65)
  rect 0.75x1.2 smd paste-0.38: 7(0,0)
  silkscreen extent -1.4,-1.25 1.4,1.25, body extent -1.3,-1.15 1.3,1.15, height 0.81
"NY PMS 440 0025 PH" [mm] "4-40 nylon screw and mounting hole"
  round 8 hole 3.2: 1(0,0)
  body extent -3.3,-3.3 3.3,3.3, height 2.69
Panduit_CXS70-14-C [mil] "Panduit"
  rect 770x500 hole 270 copper offset -74.8,0 paste-250: 1(0,0)
  body extent -960,-250 310,250, height 684
PHP0048E-MFG [mm]
  rrect33% 1.6x0.3 smd paste+0 mask+0: 1(-4.25,2.75) 2(-4.25,2.25) 3(-4.25,1.75) 4(-4.25,1.25) 5(-4.25,0.75) 6(-4.25,0.25) 7(-4.25,-0.25) 8(-4.25,-0.75) 9(-4.25,-1.25) 10(-4.25,-1.75) 11(-4.25,-2.25) 12(-4.25,-2.75) 25(4.25,-2.75) 26(4.25,-2.25) 27(4.25,-1.75) 28(4.25,-1.25) 29(4.25,-0.75) 30(4.25,-0.25) 31(4.25,0.25) 32(4.25,0.75) 33(4.25,1.25) 34(4.25,1.75) 35(4.25,2.25) 36(4.25,2.75)
  rrect33% 0.3x1.6 smd paste+0 mask+0: 13(-2.75,-4.25) 14(-2.25,-4.25) 15(-1.75,-4.25) 16(-1.25,-4.25) 17(-0.75,-4.25) 18(-0.25,-4.25) 19(0.25,-4.25) 20(0.75,-4.25) 21(1.25,-4.25) 22(1.75,-4.25) 23(2.25,-4.25) 24(2.75,-4.25) 37(2.75,4.25) 38(2.25,4.25) 39(1.75,4.25) 40(1.25,4.25) 41(0.75,4.25) 42(0.25,4.25) 43(-0.25,4.25) 44(-0.75,4.25) 45(-1.25,4.25) 46(-1.75,4.25) 47(-2.25,4.25) 48(-2.75,4.25)
  rrect2% 6.5x6.5 smd paste-1000 mask-1000: 49(0,0)
  silkscreen extent -4.38,-3.6 3.6,3.6, body extent -4.52,-4.52 4.52,4.52, height 1.2
POWERDI5 [mm] "Diodes Inc recommended land pattern, ap02001.pdf rev 60"
  rect 1.4x1.39 smd: 1(-1.991,0.92) 2(-1.991,-0.92)
  rect 4.86x3.36 smd: 3(1.991,0)
  silkscreen extent -1.7,-2.1 3.8,2.1, body extent -2.27,-2.03 4.33,2.03, height 1.17
SAMTEC_HMTSW-130-07-G-D-240 [mm] "Header, 2.54mm, 30x2, TH"
  rect 1.65x1.65 hole 1.15: 1(-1.27,36.83)
  round 1.65 hole 1.15: 2(1.27,36.83) 3(-1.27,34.29) 4(1.27,34.29) 5(-1.27,31.75) 6(1.27,31.75) 7(-1.27,29.21) 8(1.27,29.21) 9(-1.27,26.67) 10(1.27,26.67) 11(-1.27,24.13) 12(1.27,24.13) 13(-1.27,21.59) 14(1.27,21.59) 15(-1.27,19.05) 16(1.27,19.05) 17(-1.27,16.51) 18(1.27,16.51) 19(-1.27,13.97) 20(1.27,13.97) 21(-1.27,11.43) 22(1.27,11.43) 23(-1.27,8.89) 24(1.27,8.89) 25(-1.27,6.35) 26(1.27,6.35) 27(-1.27,3.81) 28(1.27,3.81) 29(-1.27,1.27) 30(1.27,1.27) 31(-1.27,-1.27) 32(1.27,-1.27) 33(-1.27,-3.81) 34(1.27,-3.81) 35(-1.27,-6.35) 36(1.27,-6.35) 37(-1.27,-8.89) 38(1.27,-8.89) 39(-1.27,-11.43) 40(1.27,-11.43) 41(-1.27,-13.97) 42(1.27,-13.97) 43(-1.27,-16.51) 44(1.27,-16.51) 45(-1.27,-19.05) 46(1.27,-19.05) 47(-1.27,-21.59) 48(1.27,-21.59) 49(-1.27,-24.13) 50(1.27,-24.13) 51(-1.27,-26.67) 52(1.27,-26.67) 53(-1.27,-29.21) 54(1.27,-29.21) 55(-1.27,-31.75) 56(1.27,-31.75) 57(-1.27,-34.29) 58(1.27,-34.29) 59(-1.27,-36.83) 60(1.27,-36.83)
  silkscreen extent -3.07,-38.1 2.54,38.1, body extent -2.54,-38.1 2.54,38.1, height 8.64
SMA [mm] "Molded Diode, 2-Leads, Body 4.3x2.6mm, IPC Medium Density, based on OnSemi component dimensions and land pattern"
  rect 2x2 smd: 1(-2,0) 2(2,0)
  silkscreen extent -3.66,-1.57 2.79,1.57, body extent -2.6,-1.3 2.6,1.3, height 2.42
SOD-123W [mm] "NXP recommended land pattern"
  rect 1.2x1.2 smd paste-0.05: 1(-1.4,0) 2(1.4,0)
  silkscreen extent -2.64,-1.14 1.68,1.14, body extent -1.85,-0.95 1.85,0.95, height 1.1
SOD-323 [mm] "NXP recommended land pattern"
  rect 0.6x0.6 smd paste-0.05: 1(-1.1,0) 2(1.1,0)
  silkscreen extent -2.06,-0.86 1.53,0.86, body extent -1.3,-0.67 1.3,0.68, height 1.1
SOD-523 [mm] "NXP Semiconductor recommended land pattern, nominal STEP model"
  rect 0.8x0.6 smd paste-0.05: 1(-0.55,0) 2(0.55,0)
  silkscreen extent -1.65,-0.66 1.2,0.66, body extent -0.8,-0.4 0.8,0.4, height 0.72
SOT-23 [mm] "SOT23, 3-Leads, Body 2.9x1.3mm, Pitch 0.95mm, Lead Span 2.5mm, IPC Medium Density"
  rrect50% 1x0.6 smd: 1(-1.2,0.95) 2(-1.2,-0.95) 3(1.2,0)
  silkscreen extent -1.63,-1.5 0.7,1.5, body extent -1.16,-1.45 1.21,1.45, height 1
TESTPOINT [mil]
  round 80 hole 37.99: 1(0,0)
  silkscreen extent -54,-53 54,53
WE-HCF_2818 [mm] "SMD, 3-Leads, Body 28.5x19.5mm"
  rect 5.59x5.33 smd: 1(-14.465,5.075) 2(-14.465,-5.075)
  rect 5.28x6.35 smd: MP(7.61,0)
  silkscreen extent -11,-14.25 9.75,14.25, body extent -16.65,-14.25 11.35,14.25, height 18.5
WL-SMCW_GREEN [mm] "WURTH"
  rect 0.8x0.8 smd: 1(-0.8,0) 2(0.8,0)
  silkscreen extent -1.9,-0.8 1.2,0.8, body extent -0.85,-0.45 0.85,0.45, height 0.8
WL-SMCW_RED [mm] "WURTH"
  rect 0.8x0.8 smd: 1(-0.8,0) 2(0.8,0)
  silkscreen extent -1.9,-0.8 1.2,0.8, body extent -0.85,-0.45 0.85,0.45, height 0.8
WL-SMCW_YELLOW [mm] "WURTH"
  rect 0.8x0.8 smd: 1(-0.8,0) 2(0.8,0)
  silkscreen extent -1.9,-0.8 1.2,0.8, body extent -0.85,-0.45 0.85,0.45, height 0.8
WURTH_61300211121 [mm] "Header, 2.54mm, 2x1, TH"
  rrect50% 1.65x1.65 hole 1.15: 1(-1.27,0)
  round 1.65 hole 1.15: 2(1.27,0)
  body extent -2.54,-1.27 2.54,1.27, height 8.54
WURTH_61300311121 [mm] "Header, 2.54mm, 3x1, TH"
  rrect50% 1.65x1.65 hole 1.15: 1(-2.54,0)
  round 1.65 hole 1.15: 2(0,0) 3(2.54,0)
  body extent -3.81,-1.27 3.81,1.27, height 8.54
